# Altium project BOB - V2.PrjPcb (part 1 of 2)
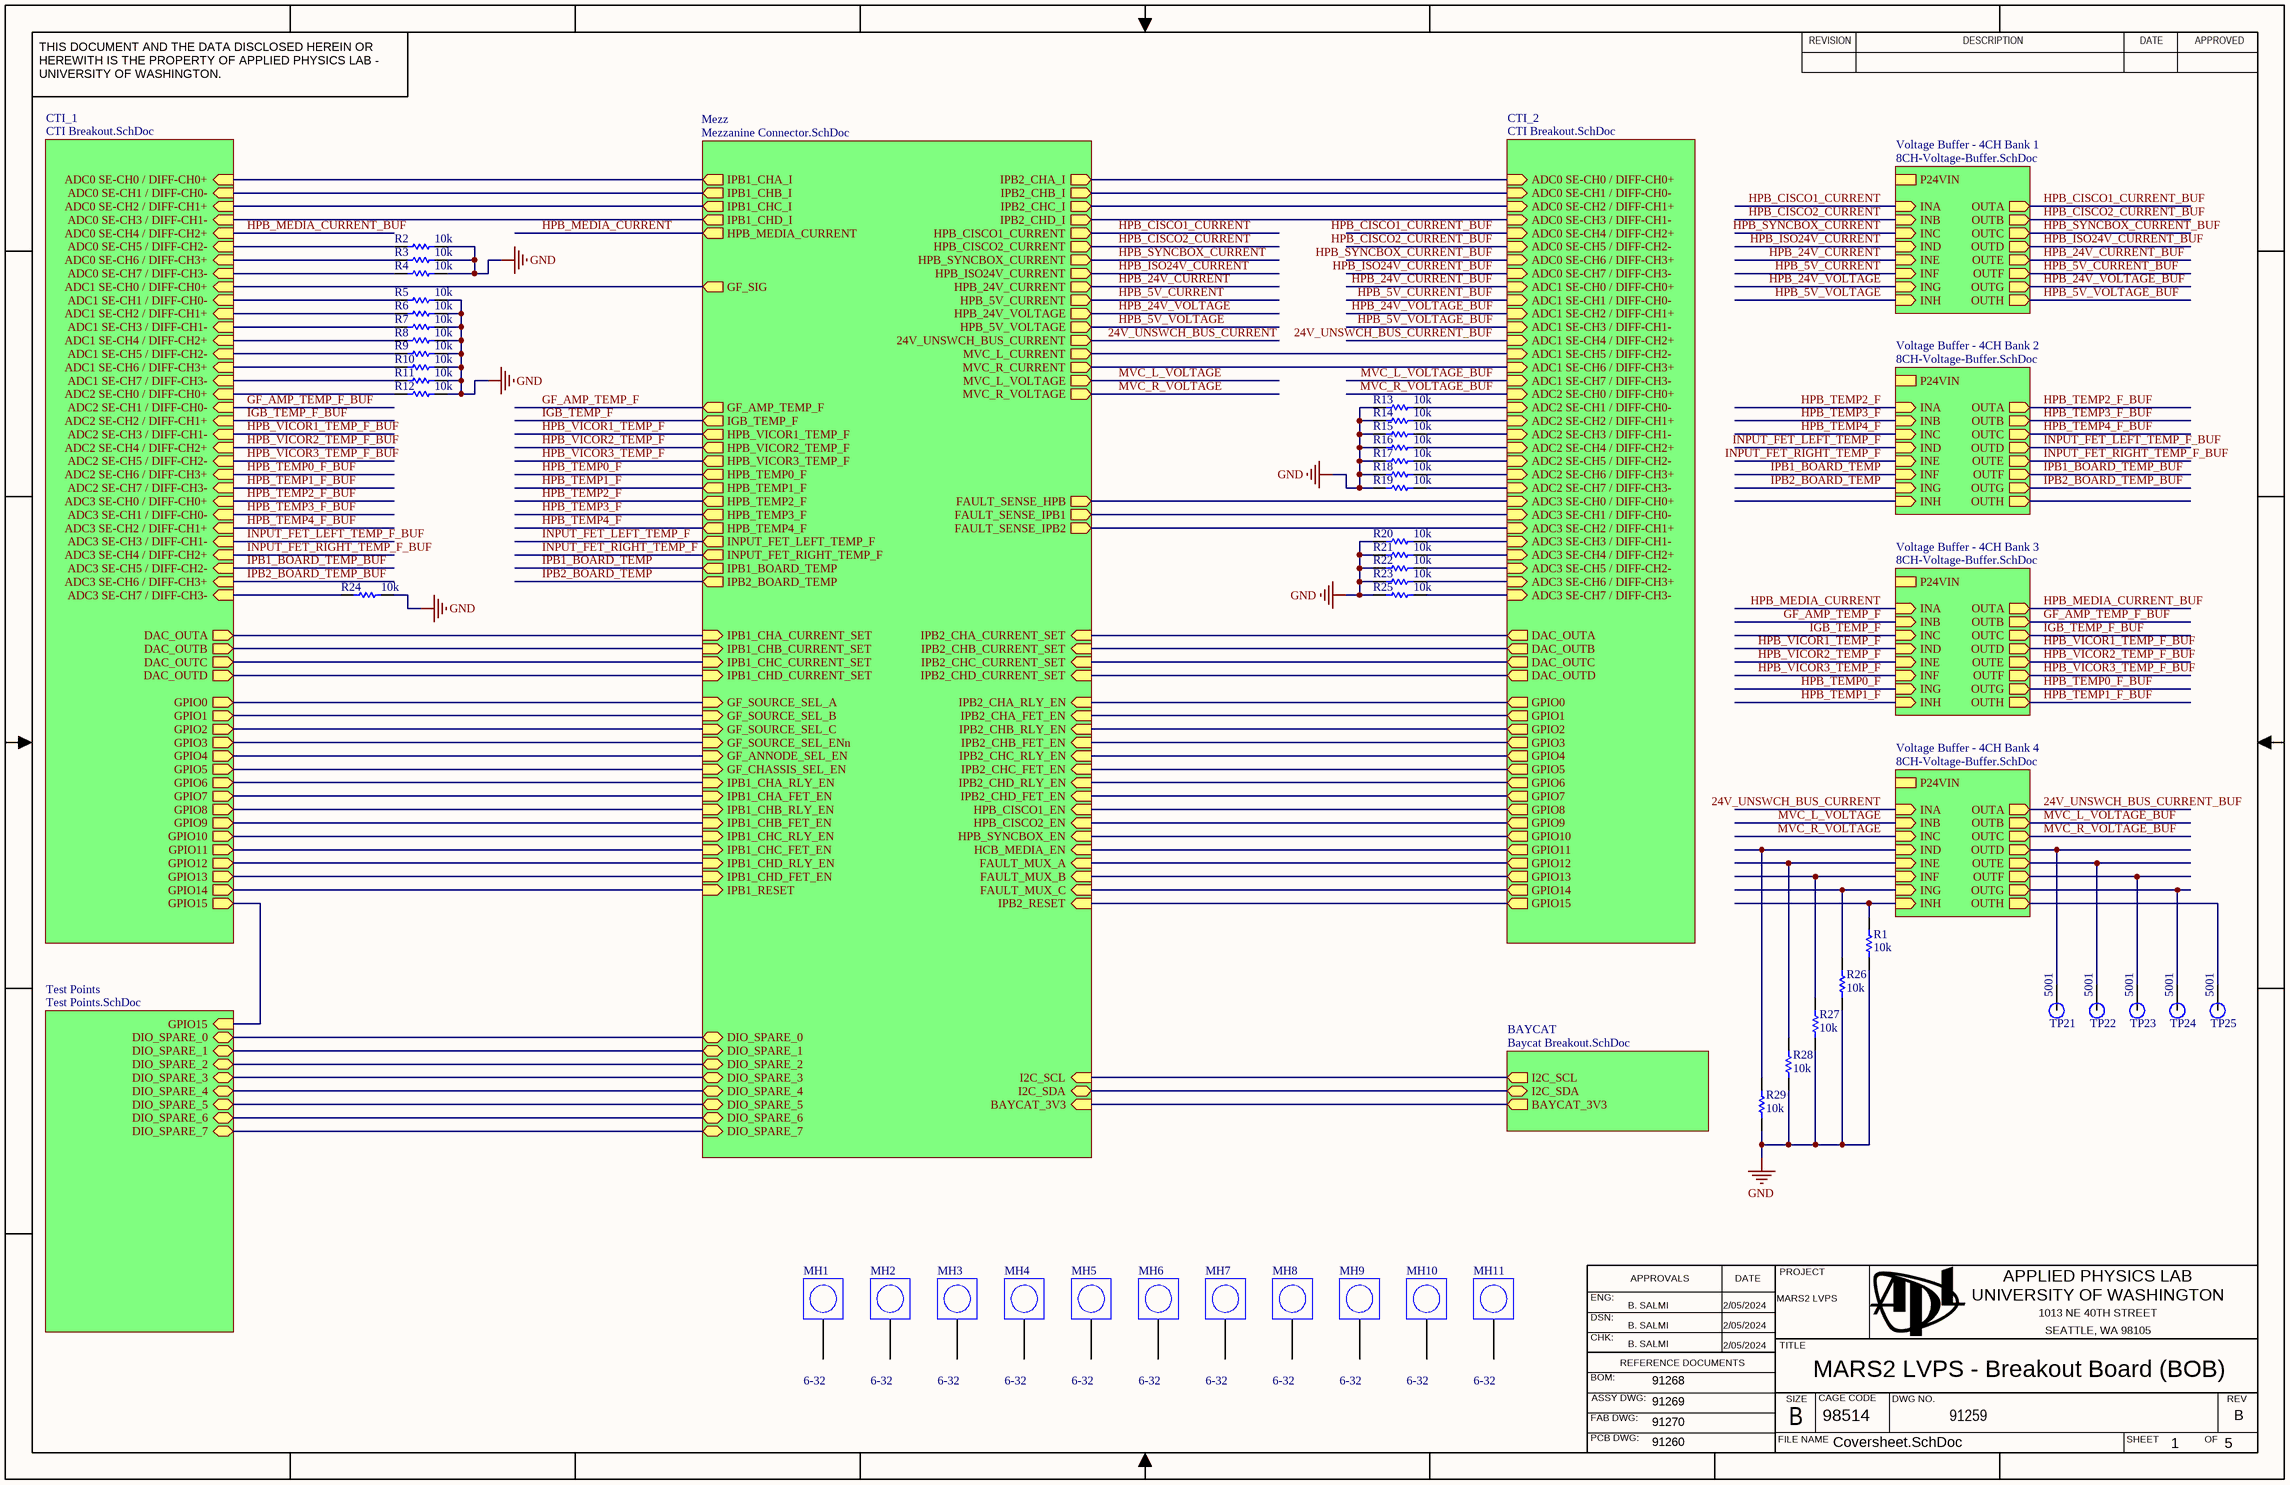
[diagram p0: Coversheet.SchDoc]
Gbl_Revision: B; Gbl_Project: MARS2 LVPS; Gbl_PCB_DWG_NO: 91260; Gbl_ENG_APP_DATE: 2/05/2024; Gbl_Engineer: B. SALMI; Gbl_DSN_APP_DATE: 2/05/2024; Gbl_DrawnBy: B. SALMI; Gbl_DOC_NO_SCH_DWG: 91259; Gbl_DOC_NO_FAB_DWG: 91270; Gbl_DOC_NO_BOM: 91268; Gbl_DOC_NO_ASSY_DWG: 91269; Gbl_CHK_APP_DATE: 2/05/2024; Gbl_CheckedBy: B. SALMI; Gbl_Cage: 98514
6 sheets, 173 parts. Net scope: hierarchical (ports join the sheet entries above them; power ports are global).
Board file: BOB.PcbDoc
Sheets:
  Coversheet.SchDoc
    Mezz = Mezzanine Connector.SchDoc
    CTI_1 = CTI Breakout.SchDoc
    CTI_2 = CTI Breakout.SchDoc
    BAYCAT = Baycat Breakout.SchDoc
    Test Points = Test Points.SchDoc
    Voltage Buffer - 4CH Bank 1 = 8CH-Voltage-Buffer.SchDoc
    Voltage Buffer - 4CH Bank 2 = 8CH-Voltage-Buffer.SchDoc
    Voltage Buffer - 4CH Bank 3 = 8CH-Voltage-Buffer.SchDoc
    Voltage Buffer - 4CH Bank 4 = 8CH-Voltage-Buffer.SchDoc

## Sheet Coversheet.SchDoc: MARS2 LVPS - Breakout Board (BOB)
size 431 x 279 mm; Organization: ORGANIZATION; Address1: APPLIED PHYSICS LAB; Address2: UNIVERSITY OF WASHINGTON; Address3: 1013 NE 40TH STREET; Address4: SEATTLE, WA 98105; DocumentNumber: 1; Revision: -; SheetNumber: 1; SheetTotal: 5; ENG_APP_DATE: --/--/--; DSN_APP_DATE: --/--/--; CHK_APP_DATE: --/--/--

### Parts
MH1  Fastener Size: 6-32  [MH-M3-Footprint-1 - Oversized MARS2]  (hidden comment: MH-MARS2-6-32)  (no BOM)
MH2  Fastener Size: 6-32  [MH-M3-Footprint-1 - Oversized MARS2]  (hidden comment: MH-MARS2-6-32)  (no BOM)
MH3  Fastener Size: 6-32  [MH-M3-Footprint-1 - Oversized MARS2]  (hidden comment: MH-MARS2-6-32)  (no BOM)
MH4  Fastener Size: 6-32  [MH-M3-Footprint-1 - Oversized MARS2]  (hidden comment: MH-MARS2-6-32)  (no BOM)
MH5  Fastener Size: 6-32  [MH-M3-Footprint-1 - Oversized MARS2]  (hidden comment: MH-MARS2-6-32)  (no BOM)
MH6  Fastener Size: 6-32  [MH-M3-Footprint-1 - Oversized MARS2]  (hidden comment: MH-MARS2-6-32)  (no BOM)
MH7  Fastener Size: 6-32  [MH-M3-Footprint-1 - Oversized MARS2]  (hidden comment: MH-MARS2-6-32)  (no BOM)
MH8  Fastener Size: 6-32  [MH-M3-Footprint-1 - Oversized MARS2]  (hidden comment: MH-MARS2-6-32)  (no BOM)
MH9  Fastener Size: 6-32  [MH-M3-Footprint-1 - Oversized MARS2]  (hidden comment: MH-MARS2-6-32)  (no BOM)
MH10  Fastener Size: 6-32  [MH-M3-Footprint-1 - Oversized MARS2]  (hidden comment: MH-MARS2-6-32)  (no BOM)
MH11  Fastener Size: 6-32  [MH-M3-Footprint-1 - Oversized MARS2]  (hidden comment: MH-MARS2-6-32)  (no BOM)
R1  value 10k  [RESC1608X55X25ML10T15]  (hidden comment: Resistor 10k +/-1% 0603 100 mW)
R2  value 10k  [RESC1608X55X25ML10T15]  (hidden comment: Resistor 10k +/-1% 0603 100 mW)
R3  value 10k  [RESC1608X55X25ML10T15]  (hidden comment: Resistor 10k +/-1% 0603 100 mW)
R4  value 10k  [RESC1608X55X25ML10T15]  (hidden comment: Resistor 10k +/-1% 0603 100 mW)
R5  value 10k  [RESC1608X55X25ML10T15]  (hidden comment: Resistor 10k +/-1% 0603 100 mW)
R6  value 10k  [RESC1608X55X25ML10T15]  (hidden comment: Resistor 10k +/-1% 0603 100 mW)
R7  value 10k  [RESC1608X55X25ML10T15]  (hidden comment: Resistor 10k +/-1% 0603 100 mW)
R8  value 10k  [RESC1608X55X25ML10T15]  (hidden comment: Resistor 10k +/-1% 0603 100 mW)
R9  value 10k  [RESC1608X55X25ML10T15]  (hidden comment: Resistor 10k +/-1% 0603 100 mW)
R10  value 10k  [RESC1608X55X25ML10T15]  (hidden comment: Resistor 10k +/-1% 0603 100 mW)
R11  value 10k  [RESC1608X55X25ML10T15]  (hidden comment: Resistor 10k +/-1% 0603 100 mW)
R12  value 10k  [RESC1608X55X25ML10T15]  (hidden comment: Resistor 10k +/-1% 0603 100 mW)
R13  value 10k  [RESC1608X55X25ML10T15]  (hidden comment: Resistor 10k +/-1% 0603 100 mW)
R14  value 10k  [RESC1608X55X25ML10T15]  (hidden comment: Resistor 10k +/-1% 0603 100 mW)
R15  value 10k  [RESC1608X55X25ML10T15]  (hidden comment: Resistor 10k +/-1% 0603 100 mW)
R16  value 10k  [RESC1608X55X25ML10T15]  (hidden comment: Resistor 10k +/-1% 0603 100 mW)
R17  value 10k  [RESC1608X55X25ML10T15]  (hidden comment: Resistor 10k +/-1% 0603 100 mW)
R18  value 10k  [RESC1608X55X25ML10T15]  (hidden comment: Resistor 10k +/-1% 0603 100 mW)
R19  value 10k  [RESC1608X55X25ML10T15]  (hidden comment: Resistor 10k +/-1% 0603 100 mW)
R20  value 10k  [RESC1608X55X25ML10T15]  (hidden comment: Resistor 10k +/-1% 0603 100 mW)
R21  value 10k  [RESC1608X55X25ML10T15]  (hidden comment: Resistor 10k +/-1% 0603 100 mW)
R22  value 10k  [RESC1608X55X25ML10T15]  (hidden comment: Resistor 10k +/-1% 0603 100 mW)
R23  value 10k  [RESC1608X55X25ML10T15]  (hidden comment: Resistor 10k +/-1% 0603 100 mW)
R24  value 10k  [RESC1608X55X25ML10T15]  (hidden comment: Resistor 10k +/-1% 0603 100 mW)
R25  value 10k  [RESC1608X55X25ML10T15]  (hidden comment: Resistor 10k +/-1% 0603 100 mW)
R26  value 10k  [RESC1608X55X25ML10T15]  (hidden comment: Resistor 10k +/-1% 0603 100 mW)
R27  value 10k  [RESC1608X55X25ML10T15]  (hidden comment: Resistor 10k +/-1% 0603 100 mW)
R28  value 10k  [RESC1608X55X25ML10T15]  (hidden comment: Resistor 10k +/-1% 0603 100 mW)
R29  value 10k  [RESC1608X55X25ML10T15]  (hidden comment: Resistor 10k +/-1% 0603 100 mW)
TP21  5001  [FP-5001-MFG]
TP22  5001  [FP-5001-MFG]
TP23  5001  [FP-5001-MFG]
TP24  5001  [FP-5001-MFG]
TP25  5001  [FP-5001-MFG]

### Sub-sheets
BAYCAT = Baycat Breakout.SchDoc: I2C_SDA (bidir), I2C_SCL (out), BAYCAT_3V3 (out)
CTI_1 = CTI Breakout.SchDoc: ADC0 SE-CH0 / DIFF-CH0+ (in), ADC0 SE-CH2 / DIFF-CH1+ (in), ADC0 SE-CH4 / DIFF-CH2+ (in), ADC0 SE-CH6 / DIFF-CH3+ (in), ADC1 SE-CH0 / DIFF-CH0+ (in), ADC1 SE-CH2 / DIFF-CH1+ (in), ADC1 SE-CH4 / DIFF-CH2+ (in), ADC1 SE-CH6 / DIFF-CH3+ (in), ADC2 SE-CH0 / DIFF-CH0+ (in), ADC2 SE-CH2 / DIFF-CH1+ (in), ADC2 SE-CH4 / DIFF-CH2+ (in), ADC2 SE-CH6 / DIFF-CH3+ (in), ADC3 SE-CH0 / DIFF-CH0+ (in), ADC3 SE-CH2 / DIFF-CH1+ (in), ADC3 SE-CH4 / DIFF-CH2+ (in), ADC3 SE-CH6 / DIFF-CH3+ (in), ADC0 SE-CH1 / DIFF-CH0- (in), ADC0 SE-CH3 / DIFF-CH1- (in), ADC0 SE-CH5 / DIFF-CH2- (in), ADC0 SE-CH7 / DIFF-CH3- (in), ADC1 SE-CH1 / DIFF-CH0- (in), ADC1 SE-CH3 / DIFF-CH1- (in), ADC1 SE-CH5 / DIFF-CH2- (in), ADC1 SE-CH7 / DIFF-CH3- (in), ADC2 SE-CH1 / DIFF-CH0- (in), ADC2 SE-CH3 / DIFF-CH1- (in), ADC2 SE-CH5 / DIFF-CH2- (in), ADC2 SE-CH7 / DIFF-CH3- (in), ADC3 SE-CH1 / DIFF-CH0- (in), ADC3 SE-CH3 / DIFF-CH1- (in), ADC3 SE-CH5 / DIFF-CH2- (in), ADC3 SE-CH7 / DIFF-CH3- (in), DAC_OUTA (out), DAC_OUTB (out), DAC_OUTC (out), DAC_OUTD (out), GPIO0 (out), GPIO2 (out), GPIO4 (out), GPIO6 (out), GPIO8 (out), GPIO10 (out), GPIO12 (out), GPIO14 (out), GPIO1 (out), GPIO3 (out), GPIO5 (out), GPIO7 (out), GPIO9 (out), GPIO11 (out), GPIO13 (out), GPIO15 (out)
CTI_2 = CTI Breakout.SchDoc: ADC0 SE-CH0 / DIFF-CH0+ (in), ADC0 SE-CH2 / DIFF-CH1+ (in), ADC0 SE-CH4 / DIFF-CH2+ (in), ADC0 SE-CH6 / DIFF-CH3+ (in), ADC1 SE-CH0 / DIFF-CH0+ (in), ADC1 SE-CH2 / DIFF-CH1+ (in), ADC1 SE-CH4 / DIFF-CH2+ (in), ADC1 SE-CH6 / DIFF-CH3+ (in), ADC2 SE-CH0 / DIFF-CH0+ (in), ADC2 SE-CH2 / DIFF-CH1+ (in), ADC2 SE-CH4 / DIFF-CH2+ (in), ADC2 SE-CH6 / DIFF-CH3+ (in), ADC3 SE-CH0 / DIFF-CH0+ (in), ADC3 SE-CH2 / DIFF-CH1+ (in), ADC3 SE-CH4 / DIFF-CH2+ (in), ADC3 SE-CH6 / DIFF-CH3+ (in), ADC0 SE-CH1 / DIFF-CH0- (in), ADC0 SE-CH3 / DIFF-CH1- (in), ADC0 SE-CH5 / DIFF-CH2- (in), ADC0 SE-CH7 / DIFF-CH3- (in), ADC1 SE-CH1 / DIFF-CH0- (in), ADC1 SE-CH3 / DIFF-CH1- (in), ADC1 SE-CH5 / DIFF-CH2- (in), ADC1 SE-CH7 / DIFF-CH3- (in), ADC2 SE-CH1 / DIFF-CH0- (in), ADC2 SE-CH3 / DIFF-CH1- (in), ADC2 SE-CH5 / DIFF-CH2- (in), ADC2 SE-CH7 / DIFF-CH3- (in), ADC3 SE-CH1 / DIFF-CH0- (in), ADC3 SE-CH3 / DIFF-CH1- (in), ADC3 SE-CH5 / DIFF-CH2- (in), ADC3 SE-CH7 / DIFF-CH3- (in), DAC_OUTA (out), DAC_OUTB (out), DAC_OUTC (out), DAC_OUTD (out), GPIO0 (out), GPIO2 (out), GPIO4 (out), GPIO6 (out), GPIO8 (out), GPIO10 (out), GPIO12 (out), GPIO14 (out), GPIO1 (out), GPIO3 (out), GPIO5 (out), GPIO7 (out), GPIO9 (out), GPIO11 (out), GPIO13 (out), GPIO15 (out)
Mezz = Mezzanine Connector.SchDoc: FAULT_SENSE_HPB (out), HPB_CISCO1_CURRENT (out), HPB_CISCO2_CURRENT (out), HPB_SYNCBOX_CURRENT (out), HPB_ISO24V_CURRENT (out), 24V_UNSWCH_BUS_CURRENT (out), HPB_24V_VOLTAGE (out), HPB_24V_CURRENT (out), HPB_5V_VOLTAGE (out), HPB_5V_CURRENT (out), FAULT_MUX_A (in), FAULT_MUX_C (in), FAULT_MUX_B (in), HPB_VICOR1_TEMP_F (out), HPB_VICOR2_TEMP_F (out), HPB_VICOR3_TEMP_F (out), HPB_TEMP0_F (out), HPB_TEMP1_F (out), HPB_TEMP2_F (out), HPB_TEMP3_F (out), HPB_TEMP4_F (out), HPB_CISCO1_EN (in), HPB_CISCO2_EN (in), HPB_SYNCBOX_EN (in), I2C_SDA (bidir), I2C_SCL (in), HCB_MEDIA_EN (in), DIO_SPARE_0 (bidir), DIO_SPARE_1 (bidir), DIO_SPARE_2 (bidir), DIO_SPARE_3 (bidir), DIO_SPARE_4 (bidir), DIO_SPARE_5 (bidir), DIO_SPARE_6 (bidir), DIO_SPARE_7 (bidir), IPB1_BOARD_TEMP (out), IPB2_BOARD_TEMP (out), BAYCAT_3V3 (in), IPB1_CHA_CURRENT_SET (in), IPB2_CHA_CURRENT_SET (in), IPB1_CHB_CURRENT_SET (in), IPB2_CHB_CURRENT_SET (in), IPB1_CHC_CURRENT_SET (in), IPB2_CHC_CURRENT_SET (in), IPB1_CHD_CURRENT_SET (in), IPB2_CHD_CURRENT_SET (in), IPB1_CHA_RLY_EN (in), IPB2_CHA_RLY_EN (in), IPB1_CHA_FET_EN (in), IPB2_CHA_FET_EN (in), IPB1_CHB_RLY_EN (in), IPB2_CHB_RLY_EN (in), IPB1_CHB_FET_EN (in), IPB2_CHB_FET_EN (in), IPB1_CHC_RLY_EN (in), IPB2_CHC_RLY_EN (in), IPB1_CHC_FET_EN (in), IPB2_CHC_FET_EN (in), IPB1_CHD_RLY_EN (in), IPB2_CHD_RLY_EN (in), IPB1_CHD_FET_EN (in), IPB2_CHD_FET_EN (in), IPB1_RESET (in), IPB2_RESET (in), MVC_R_CURRENT (out), MVC_L_CURRENT (out), MVC_R_VOLTAGE (out), MVC_L_VOLTAGE (out), GF_SOURCE_SEL_A (in), GF_SOURCE_SEL_B (in), GF_SOURCE_SEL_C (in), GF_SOURCE_SEL_ENn (in), GF_ANNODE_SEL_EN (in), GF_CHASSIS_SEL_EN (in), IPB1_CHA_I (out), IPB2_CHA_I (out), IPB1_CHB_I (out), IPB2_CHB_I (out), IPB1_CHC_I (out), IPB2_CHC_I (out), IPB1_CHD_I (out), IPB2_CHD_I (out), GF_SIG (out), FAULT_SENSE_IPB1 (out), IGB_TEMP_F (out), GF_AMP_TEMP_F (out), INPUT_FET_RIGHT_TEMP_F (out), INPUT_FET_LEFT_TEMP_F (out), FAULT_SENSE_IPB2 (out), HPB_MEDIA_CURRENT (out)
Test Points = Test Points.SchDoc: DIO_SPARE_0 (bidir), DIO_SPARE_1 (bidir), DIO_SPARE_2 (bidir), DIO_SPARE_3 (bidir), DIO_SPARE_4 (bidir), DIO_SPARE_5 (bidir), DIO_SPARE_6 (bidir), DIO_SPARE_7 (bidir), GPIO15 (in)
Voltage Buffer - 4CH Bank 1 = 8CH-Voltage-Buffer.SchDoc: P24VIN, INA (in), INB (in), INC (in), IND (in), INE (in), INF (in), ING (in), INH (in), OUTA (out), OUTB (out), OUTC (out), OUTD (out), OUTE (out), OUTF (out), OUTG (out), OUTH (out)
Voltage Buffer - 4CH Bank 2 = 8CH-Voltage-Buffer.SchDoc: P24VIN, INA (in), INB (in), INC (in), IND (in), INE (in), INF (in), ING (in), INH (in), OUTA (out), OUTB (out), OUTC (out), OUTD (out), OUTE (out), OUTF (out), OUTG (out), OUTH (out)
Voltage Buffer - 4CH Bank 3 = 8CH-Voltage-Buffer.SchDoc: P24VIN, INA (in), INB (in), INC (in), IND (in), INE (in), INF (in), ING (in), INH (in), OUTA (out), OUTB (out), OUTC (out), OUTD (out), OUTE (out), OUTF (out), OUTG (out), OUTH (out)
Voltage Buffer - 4CH Bank 4 = 8CH-Voltage-Buffer.SchDoc: P24VIN, INA (in), INB (in), INC (in), IND (in), INE (in), INF (in), ING (in), INH (in), OUTA (out), OUTB (out), OUTC (out), OUTD (out), OUTE (out), OUTF (out), OUTG (out), OUTH (out)

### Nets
GND: R1.1 R2.2 R3.2 R4.2 R5.2 R6.2 R7.2 R8.2 R9.2 R10.2 R11.2 R12.2 R13.1 R14.1 R15.1 R16.1 R17.1 R18.1 R19.1 R20.1 R21.1 R22.1 R23.1 R24.2 R25.1 R26.1 R27.1 R28.1 R29.1
24V_UNSWCH_BUS_CURRENT: sheet Mezz/24V_UNSWCH_BUS_CURRENT, sheet Voltage Buffer - 4CH Bank 4/INA
24V_UNSWCH_BUS_CURRENT_BUF: sheet CTI_2/ADC1 SE-CH4 / DIFF-CH2+, sheet Voltage Buffer - 4CH Bank 4/OUTA
BAYCAT_3V3: sheet Mezz/BAYCAT_3V3, sheet BAYCAT/BAYCAT_3V3
DIO_SPARE_0: sheet Mezz/DIO_SPARE_0, sheet Test Points/DIO_SPARE_0
DIO_SPARE_1: sheet Mezz/DIO_SPARE_1, sheet Test Points/DIO_SPARE_1
DIO_SPARE_2: sheet Mezz/DIO_SPARE_2, sheet Test Points/DIO_SPARE_2
DIO_SPARE_3: sheet Mezz/DIO_SPARE_3, sheet Test Points/DIO_SPARE_3
DIO_SPARE_4: sheet Mezz/DIO_SPARE_4, sheet Test Points/DIO_SPARE_4
DIO_SPARE_5: sheet Mezz/DIO_SPARE_5, sheet Test Points/DIO_SPARE_5
DIO_SPARE_6: sheet Mezz/DIO_SPARE_6, sheet Test Points/DIO_SPARE_6
DIO_SPARE_7: sheet Mezz/DIO_SPARE_7, sheet Test Points/DIO_SPARE_7
FAULT_MUX_A: sheet Mezz/FAULT_MUX_A, sheet CTI_2/GPIO12
FAULT_MUX_B: sheet Mezz/FAULT_MUX_B, sheet CTI_2/GPIO13
FAULT_MUX_C: sheet Mezz/FAULT_MUX_C, sheet CTI_2/GPIO14
FAULT_SENSE_HPB: sheet Mezz/FAULT_SENSE_HPB, sheet CTI_2/ADC3 SE-CH0 / DIFF-CH0+
FAULT_SENSE_IPB1: sheet Mezz/FAULT_SENSE_IPB1, sheet CTI_2/ADC3 SE-CH1 / DIFF-CH0-
FAULT_SENSE_IPB2: sheet Mezz/FAULT_SENSE_IPB2, sheet CTI_2/ADC3 SE-CH2 / DIFF-CH1+
GF_AMP_TEMP_F: sheet Mezz/GF_AMP_TEMP_F, sheet Voltage Buffer - 4CH Bank 3/INB
GF_AMP_TEMP_F_BUF: sheet CTI_1/ADC2 SE-CH1 / DIFF-CH0-, sheet Voltage Buffer - 4CH Bank 3/OUTB
GF_ANNODE_SEL_EN: sheet Mezz/GF_ANNODE_SEL_EN, sheet CTI_1/GPIO4
GF_CHASSIS_SEL_EN: sheet Mezz/GF_CHASSIS_SEL_EN, sheet CTI_1/GPIO5
GF_SIG: sheet Mezz/GF_SIG, sheet CTI_1/ADC1 SE-CH0 / DIFF-CH0+
GF_SOURCE_SEL_A: sheet Mezz/GF_SOURCE_SEL_A, sheet CTI_1/GPIO0
GF_SOURCE_SEL_B: sheet Mezz/GF_SOURCE_SEL_B, sheet CTI_1/GPIO1
GF_SOURCE_SEL_C: sheet Mezz/GF_SOURCE_SEL_C, sheet CTI_1/GPIO2
GF_SOURCE_SEL_ENn: sheet Mezz/GF_SOURCE_SEL_ENn, sheet CTI_1/GPIO3
HCB_MEDIA_EN: sheet Mezz/HCB_MEDIA_EN, sheet CTI_2/GPIO11
HPB_5V_CURRENT: sheet Mezz/HPB_5V_CURRENT, sheet Voltage Buffer - 4CH Bank 1/INF
HPB_5V_CURRENT_BUF: sheet CTI_2/ADC1 SE-CH1 / DIFF-CH0-, sheet Voltage Buffer - 4CH Bank 1/OUTF
HPB_5V_VOLTAGE: sheet Mezz/HPB_5V_VOLTAGE, sheet Voltage Buffer - 4CH Bank 1/INH
HPB_5V_VOLTAGE_BUF: sheet CTI_2/ADC1 SE-CH3 / DIFF-CH1-, sheet Voltage Buffer - 4CH Bank 1/OUTH
HPB_24V_CURRENT: sheet Mezz/HPB_24V_CURRENT, sheet Voltage Buffer - 4CH Bank 1/INE
HPB_24V_CURRENT_BUF: sheet CTI_2/ADC1 SE-CH0 / DIFF-CH0+, sheet Voltage Buffer - 4CH Bank 1/OUTE
HPB_24V_VOLTAGE: sheet Mezz/HPB_24V_VOLTAGE, sheet Voltage Buffer - 4CH Bank 1/ING
HPB_24V_VOLTAGE_BUF: sheet CTI_2/ADC1 SE-CH2 / DIFF-CH1+, sheet Voltage Buffer - 4CH Bank 1/OUTG
HPB_CISCO1_CURRENT: sheet Mezz/HPB_CISCO1_CURRENT, sheet Voltage Buffer - 4CH Bank 1/INA
HPB_CISCO1_CURRENT_BUF: sheet CTI_2/ADC0 SE-CH4 / DIFF-CH2+, sheet Voltage Buffer - 4CH Bank 1/OUTA
HPB_CISCO1_EN: sheet Mezz/HPB_CISCO1_EN, sheet CTI_2/GPIO8
HPB_CISCO2_CURRENT: sheet Mezz/HPB_CISCO2_CURRENT, sheet Voltage Buffer - 4CH Bank 1/INB
HPB_CISCO2_CURRENT_BUF: sheet CTI_2/ADC0 SE-CH5 / DIFF-CH2-, sheet Voltage Buffer - 4CH Bank 1/OUTB
HPB_CISCO2_EN: sheet Mezz/HPB_CISCO2_EN, sheet CTI_2/GPIO9
HPB_ISO24V_CURRENT: sheet Mezz/HPB_ISO24V_CURRENT, sheet Voltage Buffer - 4CH Bank 1/IND
HPB_ISO24V_CURRENT_BUF: sheet CTI_2/ADC0 SE-CH7 / DIFF-CH3-, sheet Voltage Buffer - 4CH Bank 1/OUTD
HPB_MEDIA_CURRENT: sheet Mezz/HPB_MEDIA_CURRENT, sheet Voltage Buffer - 4CH Bank 3/INA
HPB_MEDIA_CURRENT_BUF: sheet CTI_1/ADC0 SE-CH4 / DIFF-CH2+, sheet Voltage Buffer - 4CH Bank 3/OUTA
HPB_SYNCBOX_CURRENT: sheet Mezz/HPB_SYNCBOX_CURRENT, sheet Voltage Buffer - 4CH Bank 1/INC
HPB_SYNCBOX_CURRENT_BUF: sheet CTI_2/ADC0 SE-CH6 / DIFF-CH3+, sheet Voltage Buffer - 4CH Bank 1/OUTC
HPB_SYNCBOX_EN: sheet Mezz/HPB_SYNCBOX_EN, sheet CTI_2/GPIO10
HPB_TEMP0_F: sheet Mezz/HPB_TEMP0_F, sheet Voltage Buffer - 4CH Bank 3/ING  [project net HPB_TEMP0]
HPB_TEMP0_F_BUF: sheet CTI_1/ADC2 SE-CH6 / DIFF-CH3+, sheet Voltage Buffer - 4CH Bank 3/OUTG
HPB_TEMP1_F: sheet Mezz/HPB_TEMP1_F, sheet Voltage Buffer - 4CH Bank 3/INH  [project net HPB_TEMP1]
HPB_TEMP1_F_BUF: sheet CTI_1/ADC2 SE-CH7 / DIFF-CH3-, sheet Voltage Buffer - 4CH Bank 3/OUTH
HPB_TEMP2_F: sheet Mezz/HPB_TEMP2_F, sheet Voltage Buffer - 4CH Bank 2/INA  [project net HPB_TEMP2]
HPB_TEMP2_F_BUF: sheet CTI_1/ADC3 SE-CH0 / DIFF-CH0+, sheet Voltage Buffer - 4CH Bank 2/OUTA
HPB_TEMP3_F: sheet Mezz/HPB_TEMP3_F, sheet Voltage Buffer - 4CH Bank 2/INB  [project net HPB_TEMP3]
HPB_TEMP3_F_BUF: sheet CTI_1/ADC3 SE-CH1 / DIFF-CH0-, sheet Voltage Buffer - 4CH Bank 2/OUTB
HPB_TEMP4_F: sheet Mezz/HPB_TEMP4_F, sheet Voltage Buffer - 4CH Bank 2/INC  [project net HPB_TEMP4]
HPB_TEMP4_F_BUF: sheet CTI_1/ADC3 SE-CH2 / DIFF-CH1+, sheet Voltage Buffer - 4CH Bank 2/OUTC
HPB_VICOR1_TEMP_F: sheet Mezz/HPB_VICOR1_TEMP_F, sheet Voltage Buffer - 4CH Bank 3/IND  [project net HPB_VICOR1_TEMP]
HPB_VICOR1_TEMP_F_BUF: sheet CTI_1/ADC2 SE-CH3 / DIFF-CH1-, sheet Voltage Buffer - 4CH Bank 3/OUTD
HPB_VICOR2_TEMP_F: sheet Mezz/HPB_VICOR2_TEMP_F, sheet Voltage Buffer - 4CH Bank 3/INE  [project net HPB_VICOR2_TEMP]
HPB_VICOR2_TEMP_F_BUF: sheet CTI_1/ADC2 SE-CH4 / DIFF-CH2+, sheet Voltage Buffer - 4CH Bank 3/OUTE
HPB_VICOR3_TEMP_F: sheet Mezz/HPB_VICOR3_TEMP_F, sheet Voltage Buffer - 4CH Bank 3/INF  [project net HPB_VICOR3_TEMP]
HPB_VICOR3_TEMP_F_BUF: sheet CTI_1/ADC2 SE-CH5 / DIFF-CH2-, sheet Voltage Buffer - 4CH Bank 3/OUTF
I2C_SCL: sheet Mezz/I2C_SCL, sheet BAYCAT/I2C_SCL
I2C_SDA: sheet Mezz/I2C_SDA, sheet BAYCAT/I2C_SDA
IGB_TEMP_F: sheet Mezz/IGB_TEMP_F, sheet Voltage Buffer - 4CH Bank 3/INC
IGB_TEMP_F_BUF: sheet CTI_1/ADC2 SE-CH2 / DIFF-CH1+, sheet Voltage Buffer - 4CH Bank 3/OUTC
INPUT_FET_LEFT_TEMP_F: sheet Mezz/INPUT_FET_LEFT_TEMP_F, sheet Voltage Buffer - 4CH Bank 2/IND
INPUT_FET_LEFT_TEMP_F_BUF: sheet CTI_1/ADC3 SE-CH3 / DIFF-CH1-, sheet Voltage Buffer - 4CH Bank 2/OUTD
INPUT_FET_RIGHT_TEMP_F: sheet Mezz/INPUT_FET_RIGHT_TEMP_F, sheet Voltage Buffer - 4CH Bank 2/INE
INPUT_FET_RIGHT_TEMP_F_BUF: sheet CTI_1/ADC3 SE-CH4 / DIFF-CH2+, sheet Voltage Buffer - 4CH Bank 2/OUTE
IPB1_BOARD_TEMP: sheet Mezz/IPB1_BOARD_TEMP, sheet Voltage Buffer - 4CH Bank 2/INF
IPB1_BOARD_TEMP_BUF: sheet CTI_1/ADC3 SE-CH5 / DIFF-CH2-, sheet Voltage Buffer - 4CH Bank 2/OUTF
IPB1_CHA_CURRENT_SET: sheet Mezz/IPB1_CHA_CURRENT_SET, sheet CTI_1/DAC_OUTA
IPB1_CHA_FET_EN: sheet Mezz/IPB1_CHA_FET_EN, sheet CTI_1/GPIO7
IPB1_CHA_I: sheet Mezz/IPB1_CHA_I, sheet CTI_1/ADC0 SE-CH0 / DIFF-CH0+
IPB1_CHA_RLY_EN: sheet Mezz/IPB1_CHA_RLY_EN, sheet CTI_1/GPIO6
IPB1_CHB_CURRENT_SET: sheet Mezz/IPB1_CHB_CURRENT_SET, sheet CTI_1/DAC_OUTB
IPB1_CHB_FET_EN: sheet Mezz/IPB1_CHB_FET_EN, sheet CTI_1/GPIO9
IPB1_CHB_I: sheet Mezz/IPB1_CHB_I, sheet CTI_1/ADC0 SE-CH1 / DIFF-CH0-
IPB1_CHB_RLY_EN: sheet Mezz/IPB1_CHB_RLY_EN, sheet CTI_1/GPIO8
IPB1_CHC_CURRENT_SET: sheet Mezz/IPB1_CHC_CURRENT_SET, sheet CTI_1/DAC_OUTC
IPB1_CHC_FET_EN: sheet Mezz/IPB1_CHC_FET_EN, sheet CTI_1/GPIO11
IPB1_CHC_I: sheet Mezz/IPB1_CHC_I, sheet CTI_1/ADC0 SE-CH2 / DIFF-CH1+
IPB1_CHC_RLY_EN: sheet Mezz/IPB1_CHC_RLY_EN, sheet CTI_1/GPIO10
IPB1_CHD_CURRENT_SET: sheet Mezz/IPB1_CHD_CURRENT_SET, sheet CTI_1/DAC_OUTD
IPB1_CHD_FET_EN: sheet Mezz/IPB1_CHD_FET_EN, sheet CTI_1/GPIO13
IPB1_CHD_I: sheet Mezz/IPB1_CHD_I, sheet CTI_1/ADC0 SE-CH3 / DIFF-CH1-
IPB1_CHD_RLY_EN: sheet Mezz/IPB1_CHD_RLY_EN, sheet CTI_1/GPIO12
IPB1_RESET: sheet Mezz/IPB1_RESET, sheet CTI_1/GPIO14
IPB2_BOARD_TEMP: sheet Mezz/IPB2_BOARD_TEMP, sheet Voltage Buffer - 4CH Bank 2/ING
IPB2_BOARD_TEMP_BUF: sheet CTI_1/ADC3 SE-CH6 / DIFF-CH3+, sheet Voltage Buffer - 4CH Bank 2/OUTG
IPB2_CHA_CURRENT_SET: sheet Mezz/IPB2_CHA_CURRENT_SET, sheet CTI_2/DAC_OUTA
IPB2_CHA_FET_EN: sheet Mezz/IPB2_CHA_FET_EN, sheet CTI_2/GPIO1
IPB2_CHA_I: sheet Mezz/IPB2_CHA_I, sheet CTI_2/ADC0 SE-CH0 / DIFF-CH0+
IPB2_CHA_RLY_EN: sheet Mezz/IPB2_CHA_RLY_EN, sheet CTI_2/GPIO0
IPB2_CHB_CURRENT_SET: sheet Mezz/IPB2_CHB_CURRENT_SET, sheet CTI_2/DAC_OUTB
IPB2_CHB_FET_EN: sheet Mezz/IPB2_CHB_FET_EN, sheet CTI_2/GPIO3
IPB2_CHB_I: sheet Mezz/IPB2_CHB_I, sheet CTI_2/ADC0 SE-CH1 / DIFF-CH0-
IPB2_CHB_RLY_EN: sheet Mezz/IPB2_CHB_RLY_EN, sheet CTI_2/GPIO2
IPB2_CHC_CURRENT_SET: sheet Mezz/IPB2_CHC_CURRENT_SET, sheet CTI_2/DAC_OUTC
IPB2_CHC_FET_EN: sheet Mezz/IPB2_CHC_FET_EN, sheet CTI_2/GPIO5
IPB2_CHC_I: sheet Mezz/IPB2_CHC_I, sheet CTI_2/ADC0 SE-CH2 / DIFF-CH1+
IPB2_CHC_RLY_EN: sheet Mezz/IPB2_CHC_RLY_EN, sheet CTI_2/GPIO4
IPB2_CHD_CURRENT_SET: sheet Mezz/IPB2_CHD_CURRENT_SET, sheet CTI_2/DAC_OUTD
IPB2_CHD_FET_EN: sheet Mezz/IPB2_CHD_FET_EN, sheet CTI_2/GPIO7
IPB2_CHD_I: sheet Mezz/IPB2_CHD_I, sheet CTI_2/ADC0 SE-CH3 / DIFF-CH1-
IPB2_CHD_RLY_EN: sheet Mezz/IPB2_CHD_RLY_EN, sheet CTI_2/GPIO6
IPB2_RESET: sheet Mezz/IPB2_RESET, sheet CTI_2/GPIO15
MVC_L_CURRENT: sheet Mezz/MVC_L_CURRENT, sheet CTI_2/ADC1 SE-CH5 / DIFF-CH2-
MVC_L_VOLTAGE: sheet Mezz/MVC_L_VOLTAGE, sheet Voltage Buffer - 4CH Bank 4/INB
MVC_L_VOLTAGE_BUF: sheet CTI_2/ADC1 SE-CH7 / DIFF-CH3-, sheet Voltage Buffer - 4CH Bank 4/OUTB
MVC_R_CURRENT: sheet Mezz/MVC_R_CURRENT, sheet CTI_2/ADC1 SE-CH6 / DIFF-CH3+
MVC_R_VOLTAGE: sheet Mezz/MVC_R_VOLTAGE, sheet Voltage Buffer - 4CH Bank 4/INC
MVC_R_VOLTAGE_BUF: sheet CTI_2/ADC2 SE-CH0 / DIFF-CH0+, sheet Voltage Buffer - 4CH Bank 4/OUTC
NetJ19_1: sheet CTI_1/GPIO15, sheet Test Points/GPIO15
NetP1A_6: R2.1 ; sheet CTI_1/ADC0 SE-CH5 / DIFF-CH2-
NetP1A_7: R3.1 ; sheet CTI_1/ADC0 SE-CH6 / DIFF-CH3+
NetP1A_8: R4.1 ; sheet CTI_1/ADC0 SE-CH7 / DIFF-CH3-
NetP1A_12: R5.1 ; sheet CTI_1/ADC1 SE-CH1 / DIFF-CH0-
NetP1A_13: R6.1 ; sheet CTI_1/ADC1 SE-CH2 / DIFF-CH1+
NetP1A_14: R7.1 ; sheet CTI_1/ADC1 SE-CH3 / DIFF-CH1-
NetP1A_15: R8.1 ; sheet CTI_1/ADC1 SE-CH4 / DIFF-CH2+
NetP1A_16: R9.1 ; sheet CTI_1/ADC1 SE-CH5 / DIFF-CH2-
NetP1A_17: R10.1 ; sheet CTI_1/ADC1 SE-CH6 / DIFF-CH3+
NetP1A_18: R11.1 ; sheet CTI_1/ADC1 SE-CH7 / DIFF-CH3-
NetP1A_21: R12.1 ; sheet CTI_1/ADC2 SE-CH0 / DIFF-CH0+
NetP1A_38: R24.1 ; sheet CTI_1/ADC3 SE-CH7 / DIFF-CH3-
NetP1B_22: R13.2 ; sheet CTI_2/ADC2 SE-CH1 / DIFF-CH0-
NetP1B_23: R14.2 ; sheet CTI_2/ADC2 SE-CH2 / DIFF-CH1+
NetP1B_24: R15.2 ; sheet CTI_2/ADC2 SE-CH3 / DIFF-CH1-
NetP1B_25: R16.2 ; sheet CTI_2/ADC2 SE-CH4 / DIFF-CH2+
NetP1B_26: R17.2 ; sheet CTI_2/ADC2 SE-CH5 / DIFF-CH2-
NetP1B_27: R18.2 ; sheet CTI_2/ADC2 SE-CH6 / DIFF-CH3+
NetP1B_28: R19.2 ; sheet CTI_2/ADC2 SE-CH7 / DIFF-CH3-
NetP1B_34: R20.2 ; sheet CTI_2/ADC3 SE-CH3 / DIFF-CH1-
NetP1B_35: R21.2 ; sheet CTI_2/ADC3 SE-CH4 / DIFF-CH2+
NetP1B_36: R22.2 ; sheet CTI_2/ADC3 SE-CH5 / DIFF-CH2-
NetP1B_37: R23.2 ; sheet CTI_2/ADC3 SE-CH6 / DIFF-CH3+
NetP1B_38: R25.2 ; sheet CTI_2/ADC3 SE-CH7 / DIFF-CH3-
NetR1_2: R1.2 ; sheet Voltage Buffer - 4CH Bank 4/INH
NetR26_2: R26.2 ; sheet Voltage Buffer - 4CH Bank 4/ING
NetR27_2: R27.2 ; sheet Voltage Buffer - 4CH Bank 4/INF
NetR28_2: R28.2 ; sheet Voltage Buffer - 4CH Bank 4/INE
NetR29_2: R29.2 ; sheet Voltage Buffer - 4CH Bank 4/IND
NetTP3D_1: TP22.1 ; sheet Voltage Buffer - 4CH Bank 4/OUTE
NetTP7D_1: TP23.1 ; sheet Voltage Buffer - 4CH Bank 4/OUTF
NetTP11D_1: TP24.1 ; sheet Voltage Buffer - 4CH Bank 4/OUTG
NetTP15D_1: TP25.1 ; sheet Voltage Buffer - 4CH Bank 4/OUTH
NetTP16D_1: TP21.1 ; sheet Voltage Buffer - 4CH Bank 4/OUTD

Not connected (* = marked no-connect by the designer): MH1 1; MH2 1; MH3 1; MH4 1; MH5 1; MH6 1; MH7 1; MH8 1; MH9 1; MH10 1; MH11 1

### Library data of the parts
MH1-MH11 = CMP-00028-00015-1: MARS2 Project 6-32 Mounting Hole Plated .; Plated: Yes
R1-R29 = CMP-009-00017-7: Chip Resistor, 10 KOhm, +/- 1%, 01 W, -55 to 155 degC, 0603 (1608 Metric); Voltage Rating: 50V; Power: 100mW
TP21-TP25 = CMP-001-0002-3: TEST POINT PC MINI .040D BLACK

## Sheet Mezzanine Connector.SchDoc: MARS2 LVPS - BOB - Mezzanine Conn
size 431 x 279 mm; Organization: ORGANIZATION; Address1: APPLIED PHYSICS LAB; Address2: UNIVERSITY OF WASHINGTON; Address3: 1013 NE 40TH STREET; Address4: SEATTLE, WA 98105; DocumentNumber: 2; Revision: -; SheetNumber: 2; SheetTotal: 5; ENG_APP_DATE: --/--/--; DSN_APP_DATE: --/--/--; CHK_APP_DATE: --/--/--
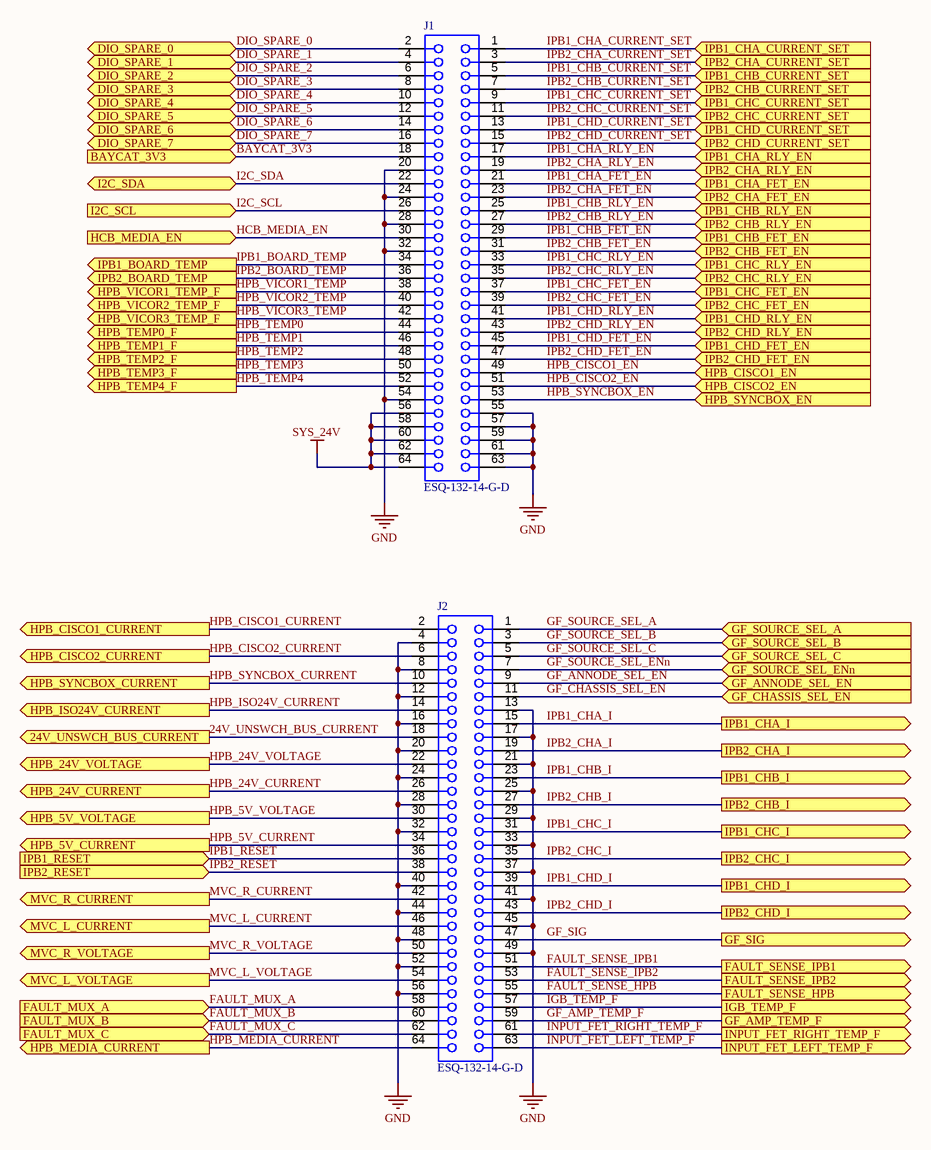
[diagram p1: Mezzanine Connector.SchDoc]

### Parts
J1  ESQ-132-14-G-D  [SMTC-ESQ-132-14-X-D]
J2  ESQ-132-14-G-D  [SMTC-ESQ-132-14-X-D]

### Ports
24V_UNSWCH_BUS_CURRENT (out), BAYCAT_3V3 (in), DIO_SPARE_0 (bidir), DIO_SPARE_1 (bidir), DIO_SPARE_2 (bidir), DIO_SPARE_3 (bidir), DIO_SPARE_4 (bidir), DIO_SPARE_5 (bidir), DIO_SPARE_6 (bidir), DIO_SPARE_7 (bidir), FAULT_MUX_A (in), FAULT_MUX_B (in), FAULT_MUX_C (in), FAULT_SENSE_HPB (out), FAULT_SENSE_IPB1 (out), FAULT_SENSE_IPB2 (out), GF_AMP_TEMP_F (out), GF_ANNODE_SEL_EN (in), GF_CHASSIS_SEL_EN (in), GF_SIG (out), GF_SOURCE_SEL_A (in), GF_SOURCE_SEL_B (in), GF_SOURCE_SEL_C (in), GF_SOURCE_SEL_ENn (in), HCB_MEDIA_EN (in), HPB_5V_CURRENT (out), HPB_5V_VOLTAGE (out), HPB_24V_CURRENT (out), HPB_24V_VOLTAGE (out), HPB_CISCO1_CURRENT (out), HPB_CISCO1_EN (in), HPB_CISCO2_CURRENT (out), HPB_CISCO2_EN (in), HPB_ISO24V_CURRENT (out), HPB_MEDIA_CURRENT (out), HPB_SYNCBOX_CURRENT (out), HPB_SYNCBOX_EN (in), HPB_TEMP0_F (out), HPB_TEMP1_F (out), HPB_TEMP2_F (out), HPB_TEMP3_F (out), HPB_TEMP4_F (out), HPB_VICOR1_TEMP_F (out), HPB_VICOR2_TEMP_F (out), HPB_VICOR3_TEMP_F (out), I2C_SCL (in), I2C_SDA (bidir), IGB_TEMP_F (out), INPUT_FET_LEFT_TEMP_F (out), INPUT_FET_RIGHT_TEMP_F (out), IPB1_BOARD_TEMP (out), IPB1_CHA_CURRENT_SET (in), IPB1_CHA_FET_EN (in), IPB1_CHA_I (out), IPB1_CHA_RLY_EN (in), IPB1_CHB_CURRENT_SET (in), IPB1_CHB_FET_EN (in), IPB1_CHB_I (out), IPB1_CHB_RLY_EN (in), IPB1_CHC_CURRENT_SET (in), IPB1_CHC_FET_EN (in), IPB1_CHC_I (out), IPB1_CHC_RLY_EN (in), IPB1_CHD_CURRENT_SET (in), IPB1_CHD_FET_EN (in), IPB1_CHD_I (out), IPB1_CHD_RLY_EN (in), IPB1_RESET (in), IPB2_BOARD_TEMP (out), IPB2_CHA_CURRENT_SET (in), IPB2_CHA_FET_EN (in), IPB2_CHA_I (out), IPB2_CHA_RLY_EN (in), IPB2_CHB_CURRENT_SET (in), IPB2_CHB_FET_EN (in), IPB2_CHB_I (out), IPB2_CHB_RLY_EN (in), IPB2_CHC_CURRENT_SET (in), IPB2_CHC_FET_EN (in), IPB2_CHC_I (out), IPB2_CHC_RLY_EN (in), IPB2_CHD_CURRENT_SET (in), IPB2_CHD_FET_EN (in), IPB2_CHD_I (out), IPB2_CHD_RLY_EN (in), IPB2_RESET (in), MVC_L_CURRENT (out), MVC_L_VOLTAGE (out), MVC_R_CURRENT (out), MVC_R_VOLTAGE (out)

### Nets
GND: J1.20 J1.24 J1.28 J1.32 J1.54 J1.55 J1.57 J1.59 J1.61 J1.63 J2.4 J2.8 J2.12 J2.13 J2.16 J2.17 J2.20 J2.21 J2.24 J2.25 J2.28 J2.29 J2.32 J2.33 J2.37 J2.40 J2.41 J2.44 J2.45 J2.48 J2.49 J2.52 J2.56
SYS_24V: J1.56 J1.58 J1.60 J1.62 J1.64
24V_UNSWCH_BUS_CURRENT: J2.18 ; port 24V_UNSWCH_BUS_CURRENT
BAYCAT_3V3: J1.18 ; port BAYCAT_3V3
DIO_SPARE_0: J1.2 ; port DIO_SPARE_0
DIO_SPARE_1: J1.4 ; port DIO_SPARE_1
DIO_SPARE_2: J1.6 ; port DIO_SPARE_2
DIO_SPARE_3: J1.8 ; port DIO_SPARE_3
DIO_SPARE_4: J1.10 ; port DIO_SPARE_4
DIO_SPARE_5: J1.12 ; port DIO_SPARE_5
DIO_SPARE_6: J1.14 ; port DIO_SPARE_6
DIO_SPARE_7: J1.16 ; port DIO_SPARE_7
FAULT_MUX_A: J2.58 ; port FAULT_MUX_A
FAULT_MUX_B: J2.60 ; port FAULT_MUX_B
FAULT_MUX_C: J2.62 ; port FAULT_MUX_C
FAULT_SENSE_HPB: J2.55 ; port FAULT_SENSE_HPB
FAULT_SENSE_IPB1: J2.51 ; port FAULT_SENSE_IPB1
FAULT_SENSE_IPB2: J2.53 ; port FAULT_SENSE_IPB2
GF_AMP_TEMP_F: J2.59 ; port GF_AMP_TEMP_F
GF_ANNODE_SEL_EN: J2.9 ; port GF_ANNODE_SEL_EN
GF_CHASSIS_SEL_EN: J2.11 ; port GF_CHASSIS_SEL_EN
GF_SIG: J2.47 ; port GF_SIG
GF_SOURCE_SEL_A: J2.1 ; port GF_SOURCE_SEL_A
GF_SOURCE_SEL_B: J2.3 ; port GF_SOURCE_SEL_B
GF_SOURCE_SEL_C: J2.5 ; port GF_SOURCE_SEL_C
GF_SOURCE_SEL_ENn: J2.7 ; port GF_SOURCE_SEL_ENn
HCB_MEDIA_EN: J1.30 ; port HCB_MEDIA_EN
HPB_5V_CURRENT: J2.34 ; port HPB_5V_CURRENT
HPB_5V_VOLTAGE: J2.30 ; port HPB_5V_VOLTAGE
HPB_24V_CURRENT: J2.26 ; port HPB_24V_CURRENT
HPB_24V_VOLTAGE: J2.22 ; port HPB_24V_VOLTAGE
HPB_CISCO1_CURRENT: J2.2 ; port HPB_CISCO1_CURRENT
HPB_CISCO1_EN: J1.49 ; port HPB_CISCO1_EN
HPB_CISCO2_CURRENT: J2.6 ; port HPB_CISCO2_CURRENT
HPB_CISCO2_EN: J1.51 ; port HPB_CISCO2_EN
HPB_ISO24V_CURRENT: J2.14 ; port HPB_ISO24V_CURRENT
HPB_MEDIA_CURRENT: J2.64 ; port HPB_MEDIA_CURRENT
HPB_SYNCBOX_CURRENT: J2.10 ; port HPB_SYNCBOX_CURRENT
HPB_SYNCBOX_EN: J1.53 ; port HPB_SYNCBOX_EN
HPB_TEMP0: J1.44 ; port HPB_TEMP0_F
HPB_TEMP1: J1.46 ; port HPB_TEMP1_F
HPB_TEMP2: J1.48 ; port HPB_TEMP2_F
HPB_TEMP3: J1.50 ; port HPB_TEMP3_F
HPB_TEMP4: J1.52 ; port HPB_TEMP4_F
HPB_VICOR1_TEMP: J1.38 ; port HPB_VICOR1_TEMP_F
HPB_VICOR2_TEMP: J1.40 ; port HPB_VICOR2_TEMP_F
HPB_VICOR3_TEMP: J1.42 ; port HPB_VICOR3_TEMP_F
I2C_SCL: J1.26 ; port I2C_SCL
I2C_SDA: J1.22 ; port I2C_SDA
IGB_TEMP_F: J2.57 ; port IGB_TEMP_F
INPUT_FET_LEFT_TEMP_F: J2.63 ; port INPUT_FET_LEFT_TEMP_F
INPUT_FET_RIGHT_TEMP_F: J2.61 ; port INPUT_FET_RIGHT_TEMP_F
IPB1_BOARD_TEMP: J1.34 ; port IPB1_BOARD_TEMP
IPB1_CHA_CURRENT_SET: J1.1 ; port IPB1_CHA_CURRENT_SET
IPB1_CHA_FET_EN: J1.21 ; port IPB1_CHA_FET_EN
IPB1_CHA_I: J2.15 ; port IPB1_CHA_I
IPB1_CHA_RLY_EN: J1.17 ; port IPB1_CHA_RLY_EN
IPB1_CHB_CURRENT_SET: J1.5 ; port IPB1_CHB_CURRENT_SET
IPB1_CHB_FET_EN: J1.29 ; port IPB1_CHB_FET_EN
IPB1_CHB_I: J2.23 ; port IPB1_CHB_I
IPB1_CHB_RLY_EN: J1.25 ; port IPB1_CHB_RLY_EN
IPB1_CHC_CURRENT_SET: J1.9 ; port IPB1_CHC_CURRENT_SET
IPB1_CHC_FET_EN: J1.37 ; port IPB1_CHC_FET_EN
IPB1_CHC_I: J2.31 ; port IPB1_CHC_I
IPB1_CHC_RLY_EN: J1.33 ; port IPB1_CHC_RLY_EN
IPB1_CHD_CURRENT_SET: J1.13 ; port IPB1_CHD_CURRENT_SET
IPB1_CHD_FET_EN: J1.45 ; port IPB1_CHD_FET_EN
IPB1_CHD_I: J2.39 ; port IPB1_CHD_I
IPB1_CHD_RLY_EN: J1.41 ; port IPB1_CHD_RLY_EN
IPB1_RESET: J2.36 ; port IPB1_RESET
IPB2_BOARD_TEMP: J1.36 ; port IPB2_BOARD_TEMP
IPB2_CHA_CURRENT_SET: J1.3 ; port IPB2_CHA_CURRENT_SET
IPB2_CHA_FET_EN: J1.23 ; port IPB2_CHA_FET_EN
IPB2_CHA_I: J2.19 ; port IPB2_CHA_I
IPB2_CHA_RLY_EN: J1.19 ; port IPB2_CHA_RLY_EN
IPB2_CHB_CURRENT_SET: J1.7 ; port IPB2_CHB_CURRENT_SET
IPB2_CHB_FET_EN: J1.31 ; port IPB2_CHB_FET_EN
IPB2_CHB_I: J2.27 ; port IPB2_CHB_I
IPB2_CHB_RLY_EN: J1.27 ; port IPB2_CHB_RLY_EN
IPB2_CHC_CURRENT_SET: J1.11 ; port IPB2_CHC_CURRENT_SET
IPB2_CHC_FET_EN: J1.39 ; port IPB2_CHC_FET_EN
IPB2_CHC_I: J2.35 ; port IPB2_CHC_I
IPB2_CHC_RLY_EN: J1.35 ; port IPB2_CHC_RLY_EN
IPB2_CHD_CURRENT_SET: J1.15 ; port IPB2_CHD_CURRENT_SET
IPB2_CHD_FET_EN: J1.47 ; port IPB2_CHD_FET_EN
IPB2_CHD_I: J2.43 ; port IPB2_CHD_I
IPB2_CHD_RLY_EN: J1.43 ; port IPB2_CHD_RLY_EN
IPB2_RESET: J2.38 ; port IPB2_RESET
MVC_L_CURRENT: J2.46 ; port MVC_L_CURRENT
MVC_L_VOLTAGE: J2.54 ; port MVC_L_VOLTAGE
MVC_R_CURRENT: J2.42 ; port MVC_R_CURRENT
MVC_R_VOLTAGE: J2.50 ; port MVC_R_VOLTAGE

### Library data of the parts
J1 J2 = CMP-002-00093-2: Conn Elevated Socket SKT 64 POS 2.54mm Solder ST Top Entry Thru-Hole Tube; Voltage Rating (AC): 550V; Current Rating: 6.9A; Number of Contacts: 64; Row Spacing: 0.1inch; Connector Type: Receptacle; Contact Resistance: 10mR

## Sheet CTI Breakout.SchDoc: MARS2 LVPS - BOB - CTI Breakout
size 431 x 279 mm; Organization: ORGANIZATION; Address1: APPLIED PHYSICS LAB; Address2: UNIVERSITY OF WASHINGTON; Address3: 1013 NE 40TH STREET; Address4: SEATTLE, WA 98105; DocumentNumber: 3; Revision: -; SheetNumber: 3; SheetTotal: 5; ENG_APP_DATE: --/--/--; DSN_APP_DATE: --/--/--; CHK_APP_DATE: --/--/--
Used 2 times, as channels CTI_1, CTI_2. Parts and nets are listed once, with the designators drawn on the sheet.
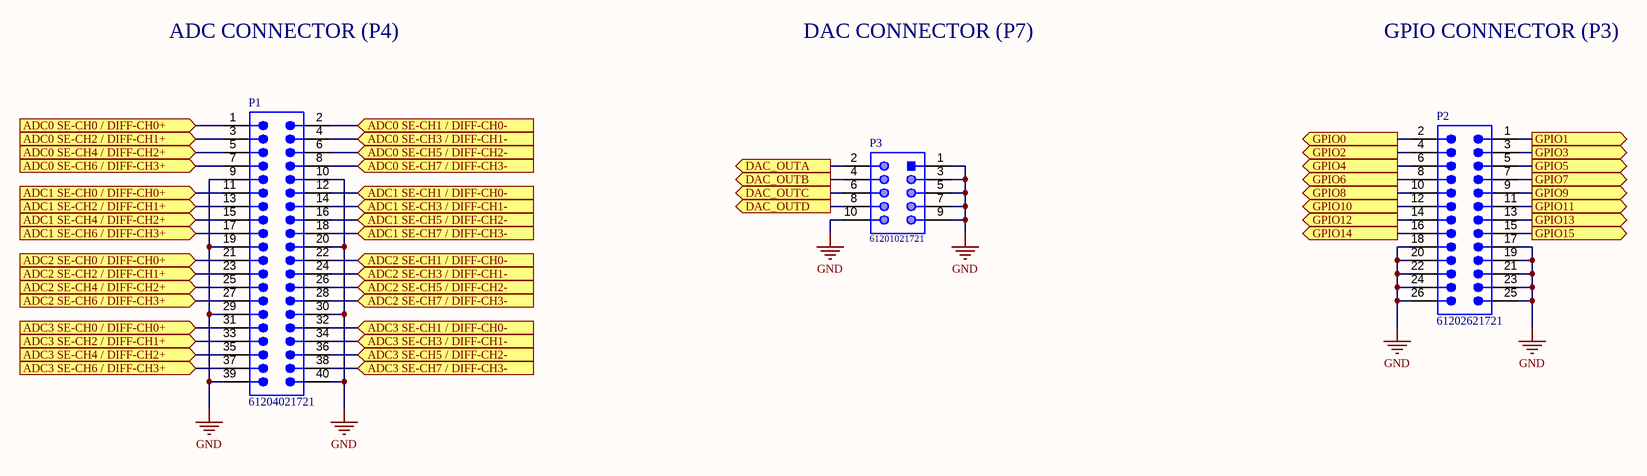
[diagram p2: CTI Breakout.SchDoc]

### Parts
P1  61204021721  [61204021721]
P2  61202621721  [61202621721]
P3  61201021721  [61201021721]

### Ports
ADC0 SE-CH0 / DIFF-CH0+ (in), ADC0 SE-CH1 / DIFF-CH0- (in), ADC0 SE-CH2 / DIFF-CH1+ (in), ADC0 SE-CH3 / DIFF-CH1- (in), ADC0 SE-CH4 / DIFF-CH2+ (in), ADC0 SE-CH5 / DIFF-CH2- (in), ADC0 SE-CH6 / DIFF-CH3+ (in), ADC0 SE-CH7 / DIFF-CH3- (in), ADC1 SE-CH0 / DIFF-CH0+ (in), ADC1 SE-CH1 / DIFF-CH0- (in), ADC1 SE-CH2 / DIFF-CH1+ (in), ADC1 SE-CH3 / DIFF-CH1- (in), ADC1 SE-CH4 / DIFF-CH2+ (in), ADC1 SE-CH5 / DIFF-CH2- (in), ADC1 SE-CH6 / DIFF-CH3+ (in), ADC1 SE-CH7 / DIFF-CH3- (in), ADC2 SE-CH0 / DIFF-CH0+ (in), ADC2 SE-CH1 / DIFF-CH0- (in), ADC2 SE-CH2 / DIFF-CH1+ (in), ADC2 SE-CH3 / DIFF-CH1- (in), ADC2 SE-CH4 / DIFF-CH2+ (in), ADC2 SE-CH5 / DIFF-CH2- (in), ADC2 SE-CH6 / DIFF-CH3+ (in), ADC2 SE-CH7 / DIFF-CH3- (in), ADC3 SE-CH0 / DIFF-CH0+ (in), ADC3 SE-CH1 / DIFF-CH0- (in), ADC3 SE-CH2 / DIFF-CH1+ (in), ADC3 SE-CH3 / DIFF-CH1- (in), ADC3 SE-CH4 / DIFF-CH2+ (in), ADC3 SE-CH5 / DIFF-CH2- (in), ADC3 SE-CH6 / DIFF-CH3+ (in), ADC3 SE-CH7 / DIFF-CH3- (in), DAC_OUTA (out), DAC_OUTB (out), DAC_OUTC (out), DAC_OUTD (out), GPIO0 (out), GPIO1 (out), GPIO2 (out), GPIO3 (out), GPIO4 (out), GPIO5 (out), GPIO6 (out), GPIO7 (out), GPIO8 (out), GPIO9 (out), GPIO10 (out), GPIO11 (out), GPIO12 (out), GPIO13 (out), GPIO14 (out), GPIO15 (out)

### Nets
GND: P1.9 P1.10 P1.19 P1.20 P1.29 P1.30 P1.39 P1.40 P2.17 P2.18 P2.19 P2.20 P2.21 P2.22 P2.23 P2.24 P2.25 P2.26 P3.1 P3.3 P3.5 P3.7 P3.9 P3.10
ADC0 SE-CH0 / DIFF-CH0+: P1.1 ; port ADC0 SE-CH0 / DIFF-CH0+
ADC0 SE-CH1 / DIFF-CH0-: P1.2 ; port ADC0 SE-CH1 / DIFF-CH0-
ADC0 SE-CH2 / DIFF-CH1+: P1.3 ; port ADC0 SE-CH2 / DIFF-CH1+
ADC0 SE-CH3 / DIFF-CH1-: P1.4 ; port ADC0 SE-CH3 / DIFF-CH1-
ADC0 SE-CH4 / DIFF-CH2+: P1.5 ; port ADC0 SE-CH4 / DIFF-CH2+
ADC0 SE-CH5 / DIFF-CH2-: P1.6 ; port ADC0 SE-CH5 / DIFF-CH2-
ADC0 SE-CH6 / DIFF-CH3+: P1.7 ; port ADC0 SE-CH6 / DIFF-CH3+
ADC0 SE-CH7 / DIFF-CH3-: P1.8 ; port ADC0 SE-CH7 / DIFF-CH3-
ADC1 SE-CH0 / DIFF-CH0+: P1.11 ; port ADC1 SE-CH0 / DIFF-CH0+
ADC1 SE-CH1 / DIFF-CH0-: P1.12 ; port ADC1 SE-CH1 / DIFF-CH0-
ADC1 SE-CH2 / DIFF-CH1+: P1.13 ; port ADC1 SE-CH2 / DIFF-CH1+
ADC1 SE-CH3 / DIFF-CH1-: P1.14 ; port ADC1 SE-CH3 / DIFF-CH1-
ADC1 SE-CH4 / DIFF-CH2+: P1.15 ; port ADC1 SE-CH4 / DIFF-CH2+
ADC1 SE-CH5 / DIFF-CH2-: P1.16 ; port ADC1 SE-CH5 / DIFF-CH2-
ADC1 SE-CH6 / DIFF-CH3+: P1.17 ; port ADC1 SE-CH6 / DIFF-CH3+
ADC1 SE-CH7 / DIFF-CH3-: P1.18 ; port ADC1 SE-CH7 / DIFF-CH3-
ADC2 SE-CH0 / DIFF-CH0+: P1.21 ; port ADC2 SE-CH0 / DIFF-CH0+
ADC2 SE-CH1 / DIFF-CH0-: P1.22 ; port ADC2 SE-CH1 / DIFF-CH0-
ADC2 SE-CH2 / DIFF-CH1+: P1.23 ; port ADC2 SE-CH2 / DIFF-CH1+
ADC2 SE-CH3 / DIFF-CH1-: P1.24 ; port ADC2 SE-CH3 / DIFF-CH1-
ADC2 SE-CH4 / DIFF-CH2+: P1.25 ; port ADC2 SE-CH4 / DIFF-CH2+
ADC2 SE-CH5 / DIFF-CH2-: P1.26 ; port ADC2 SE-CH5 / DIFF-CH2-
ADC2 SE-CH6 / DIFF-CH3+: P1.27 ; port ADC2 SE-CH6 / DIFF-CH3+
ADC2 SE-CH7 / DIFF-CH3-: P1.28 ; port ADC2 SE-CH7 / DIFF-CH3-
ADC3 SE-CH0 / DIFF-CH0+: P1.31 ; port ADC3 SE-CH0 / DIFF-CH0+
ADC3 SE-CH1 / DIFF-CH0-: P1.32 ; port ADC3 SE-CH1 / DIFF-CH0-
ADC3 SE-CH2 / DIFF-CH1+: P1.33 ; port ADC3 SE-CH2 / DIFF-CH1+
ADC3 SE-CH3 / DIFF-CH1-: P1.34 ; port ADC3 SE-CH3 / DIFF-CH1-
ADC3 SE-CH4 / DIFF-CH2+: P1.35 ; port ADC3 SE-CH4 / DIFF-CH2+
ADC3 SE-CH5 / DIFF-CH2-: P1.36 ; port ADC3 SE-CH5 / DIFF-CH2-
ADC3 SE-CH6 / DIFF-CH3+: P1.37 ; port ADC3 SE-CH6 / DIFF-CH3+
ADC3 SE-CH7 / DIFF-CH3-: P1.38 ; port ADC3 SE-CH7 / DIFF-CH3-
DAC_OUTA: P3.2 ; port DAC_OUTA
DAC_OUTB: P3.4 ; port DAC_OUTB
DAC_OUTC: P3.6 ; port DAC_OUTC
DAC_OUTD: P3.8 ; port DAC_OUTD
GPIO0: P2.2 ; port GPIO0
GPIO1: P2.1 ; port GPIO1
GPIO2: P2.4 ; port GPIO2
GPIO3: P2.3 ; port GPIO3
GPIO4: P2.6 ; port GPIO4
GPIO5: P2.5 ; port GPIO5
GPIO6: P2.8 ; port GPIO6
GPIO7: P2.7 ; port GPIO7
GPIO8: P2.10 ; port GPIO8
GPIO9: P2.9 ; port GPIO9
GPIO10: P2.12 ; port GPIO10
GPIO11: P2.11 ; port GPIO11
GPIO12: P2.14 ; port GPIO12
GPIO13: P2.13 ; port GPIO13
GPIO14: P2.16 ; port GPIO14
GPIO15: P2.15 ; port GPIO15

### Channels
CTI_1: designators end in A; ports ADC0 SE-CH0 / DIFF-CH0+=IPB1_CHA_I ADC0 SE-CH1 / DIFF-CH0-=IPB1_CHB_I ADC0 SE-CH2 / DIFF-CH1+=IPB1_CHC_I ADC0 SE-CH3 / DIFF-CH1-=IPB1_CHD_I ADC0 SE-CH4 / DIFF-CH2+=HPB_MEDIA_CURRENT_BUF ADC0 SE-CH5 / DIFF-CH2-=NetP1A_6 ADC0 SE-CH6 / DIFF-CH3+=NetP1A_7 ADC0 SE-CH7 / DIFF-CH3-=NetP1A_8 ADC1 SE-CH0 / DIFF-CH0+=GF_SIG ADC1 SE-CH1 / DIFF-CH0-=NetP1A_12 ADC1 SE-CH2 / DIFF-CH1+=NetP1A_13 ADC1 SE-CH3 / DIFF-CH1-=NetP1A_14 ADC1 SE-CH4 / DIFF-CH2+=NetP1A_15 ADC1 SE-CH5 / DIFF-CH2-=NetP1A_16 ADC1 SE-CH6 / DIFF-CH3+=NetP1A_17 ADC1 SE-CH7 / DIFF-CH3-=NetP1A_18 ADC2 SE-CH0 / DIFF-CH0+=NetP1A_21 ADC2 SE-CH1 / DIFF-CH0-=GF_AMP_TEMP_F_BUF ADC2 SE-CH2 / DIFF-CH1+=IGB_TEMP_F_BUF ADC2 SE-CH3 / DIFF-CH1-=HPB_VICOR1_TEMP_F_BUF ADC2 SE-CH4 / DIFF-CH2+=HPB_VICOR2_TEMP_F_BUF ADC2 SE-CH5 / DIFF-CH2-=HPB_VICOR3_TEMP_F_BUF ADC2 SE-CH6 / DIFF-CH3+=HPB_TEMP0_F_BUF ADC2 SE-CH7 / DIFF-CH3-=HPB_TEMP1_F_BUF ADC3 SE-CH0 / DIFF-CH0+=HPB_TEMP2_F_BUF ADC3 SE-CH1 / DIFF-CH0-=HPB_TEMP3_F_BUF ADC3 SE-CH2 / DIFF-CH1+=HPB_TEMP4_F_BUF ADC3 SE-CH3 / DIFF-CH1-=INPUT_FET_LEFT_TEMP_F_BUF ADC3 SE-CH4 / DIFF-CH2+=INPUT_FET_RIGHT_TEMP_F_BUF ADC3 SE-CH5 / DIFF-CH2-=IPB1_BOARD_TEMP_BUF ADC3 SE-CH6 / DIFF-CH3+=IPB2_BOARD_TEMP_BUF ADC3 SE-CH7 / DIFF-CH3-=NetP1A_38 DAC_OUTA=IPB1_CHA_CURRENT_SET DAC_OUTB=IPB1_CHB_CURRENT_SET DAC_OUTC=IPB1_CHC_CURRENT_SET DAC_OUTD=IPB1_CHD_CURRENT_SET GPIO0=GF_SOURCE_SEL_A GPIO1=GF_SOURCE_SEL_B GPIO2=GF_SOURCE_SEL_C GPIO3=GF_SOURCE_SEL_ENn GPIO4=GF_ANNODE_SEL_EN GPIO5=GF_CHASSIS_SEL_EN GPIO6=IPB1_CHA_RLY_EN GPIO7=IPB1_CHA_FET_EN GPIO8=IPB1_CHB_RLY_EN GPIO9=IPB1_CHB_FET_EN GPIO10=IPB1_CHC_RLY_EN GPIO11=IPB1_CHC_FET_EN GPIO12=IPB1_CHD_RLY_EN GPIO13=IPB1_CHD_FET_EN GPIO14=IPB1_RESET GPIO15=NetJ19_1
CTI_2: designators end in B; ports ADC0 SE-CH0 / DIFF-CH0+=IPB2_CHA_I ADC0 SE-CH1 / DIFF-CH0-=IPB2_CHB_I ADC0 SE-CH2 / DIFF-CH1+=IPB2_CHC_I ADC0 SE-CH3 / DIFF-CH1-=IPB2_CHD_I ADC0 SE-CH4 / DIFF-CH2+=HPB_CISCO1_CURRENT_BUF ADC0 SE-CH5 / DIFF-CH2-=HPB_CISCO2_CURRENT_BUF ADC0 SE-CH6 / DIFF-CH3+=HPB_SYNCBOX_CURRENT_BUF ADC0 SE-CH7 / DIFF-CH3-=HPB_ISO24V_CURRENT_BUF ADC1 SE-CH0 / DIFF-CH0+=HPB_24V_CURRENT_BUF ADC1 SE-CH1 / DIFF-CH0-=HPB_5V_CURRENT_BUF ADC1 SE-CH2 / DIFF-CH1+=HPB_24V_VOLTAGE_BUF ADC1 SE-CH3 / DIFF-CH1-=HPB_5V_VOLTAGE_BUF ADC1 SE-CH4 / DIFF-CH2+=24V_UNSWCH_BUS_CURRENT_BUF ADC1 SE-CH5 / DIFF-CH2-=MVC_L_CURRENT ADC1 SE-CH6 / DIFF-CH3+=MVC_R_CURRENT ADC1 SE-CH7 / DIFF-CH3-=MVC_L_VOLTAGE_BUF ADC2 SE-CH0 / DIFF-CH0+=MVC_R_VOLTAGE_BUF ADC2 SE-CH1 / DIFF-CH0-=NetP1B_22 ADC2 SE-CH2 / DIFF-CH1+=NetP1B_23 ADC2 SE-CH3 / DIFF-CH1-=NetP1B_24 ADC2 SE-CH4 / DIFF-CH2+=NetP1B_25 ADC2 SE-CH5 / DIFF-CH2-=NetP1B_26 ADC2 SE-CH6 / DIFF-CH3+=NetP1B_27 ADC2 SE-CH7 / DIFF-CH3-=NetP1B_28 ADC3 SE-CH0 / DIFF-CH0+=FAULT_SENSE_HPB ADC3 SE-CH1 / DIFF-CH0-=FAULT_SENSE_IPB1 ADC3 SE-CH2 / DIFF-CH1+=FAULT_SENSE_IPB2 ADC3 SE-CH3 / DIFF-CH1-=NetP1B_34 ADC3 SE-CH4 / DIFF-CH2+=NetP1B_35 ADC3 SE-CH5 / DIFF-CH2-=NetP1B_36 ADC3 SE-CH6 / DIFF-CH3+=NetP1B_37 ADC3 SE-CH7 / DIFF-CH3-=NetP1B_38 DAC_OUTA=IPB2_CHA_CURRENT_SET DAC_OUTB=IPB2_CHB_CURRENT_SET DAC_OUTC=IPB2_CHC_CURRENT_SET DAC_OUTD=IPB2_CHD_CURRENT_SET GPIO0=IPB2_CHA_RLY_EN GPIO1=IPB2_CHA_FET_EN GPIO2=IPB2_CHB_RLY_EN GPIO3=IPB2_CHB_FET_EN GPIO4=IPB2_CHC_RLY_EN GPIO5=IPB2_CHC_FET_EN GPIO6=IPB2_CHD_RLY_EN GPIO7=IPB2_CHD_FET_EN GPIO8=HPB_CISCO1_EN GPIO9=HPB_CISCO2_EN GPIO10=HPB_SYNCBOX_EN GPIO11=HCB_MEDIA_EN GPIO12=FAULT_MUX_A GPIO13=FAULT_MUX_B GPIO14=FAULT_MUX_C GPIO15=IPB2_RESET

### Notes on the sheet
- ADC CONNECTOR (P4)
- DAC CONNECTOR (P7)
- GPIO CONNECTOR (P3)

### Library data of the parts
P1 = CMP-002-00158-1: WR-BHD Angled Male, Box Header, Through Hole, 2 Rows, 40 Contacts, 2.54mm Pitch; Number of Contacts: 40; Current Rating: 3A; Voltage Rating: 250V
P2 = CMP-002-00157-1: WR-BHD Angled Male, Box Header, Through Hole, 2 Rows, 26 Contacts, 2.54mm Pitch; Number of Contacts: 26; Current Rating: 3A; Voltage Rating: 250V; Row Spacing: 0.1inch
P3 = CMP-002-00155-1: WR-BHD Angled Male, Box Header, Through Hole, 2 Rows, 10 Contacts, 2.54mm Pitch; Voltage Rating: 250V; Current Rating: 3A; Number of Contacts: 10

## Sheet Baycat Breakout.SchDoc: MARS2 LVPS - BOB - Baycat Breakout
size 431 x 279 mm; Organization: ORGANIZATION; Address1: APPLIED PHYSICS LAB; Address2: UNIVERSITY OF WASHINGTON; Address3: 1013 NE 40TH STREET; Address4: SEATTLE, WA 98105; DocumentNumber: 4; Revision: -; SheetNumber: 4; SheetTotal: 5; ENG_APP_DATE: --/--/--; DSN_APP_DATE: --/--/--; CHK_APP_DATE: --/--/--
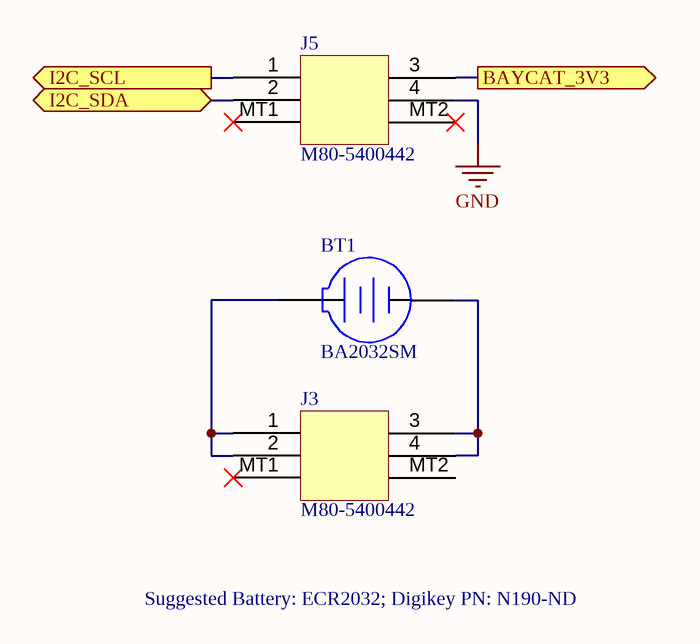
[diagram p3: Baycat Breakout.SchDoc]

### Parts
BT1  BA2032SM  [MPD-BA2032SM_V]
J3  M80-5400442  [M80-5400442-Footprint-1]
J5  M80-5400442  [M80-5400442-Footprint-1]

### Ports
BAYCAT_3V3 (out), I2C_SCL (out), I2C_SDA (bidir)

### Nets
GND: J5.4
BAYCAT_3V3: J5.3 ; port BAYCAT_3V3
I2C_SCL: J5.1 ; port I2C_SCL
I2C_SDA: J5.2 ; port I2C_SDA
NetBT1_1: BT1.1(+) J3.1 J3.2
NetBT1_2: BT1.2(-) J3.3 J3.4

Not connected (* = marked no-connect by the designer): J3 MT1* MT2; J5 MT1* MT2*

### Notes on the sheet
- Suggested Battery: ECR2032; Digikey PN: N190-ND

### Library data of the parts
BT1 = CMP-002-00003-2: Coin Cell Holder, 1 Cell, -40 to 225 degC, 2-Pin SMD, RoHS, Tray; Manufacturer: Memory Protection Devices; Connector Type: BatteryHolder
J3 J5 = CMP-002-00095-3: HARWIN - M80-5400442 - Wire-To-Board Connector, 2 mm, 4 Contacts, Header, Datamate J-Tek M80 Series, Through Hole, 2 Rows; Maximum Voltage: 800V; Gender: Male; Number of Contacts: 4; Pitch: 2mm; Current Rating: 2.2A; Contact Resistance: 25mR; Insulation Resistance: 100MR

## Sheet Test Points.SchDoc: MARS2 LVPS - BOB - Test Points
size 431 x 279 mm; Organization: ORGANIZATION; Address1: APPLIED PHYSICS LAB; Address2: UNIVERSITY OF WASHINGTON; Address3: 1013 NE 40TH STREET; Address4: SEATTLE, WA 98105; DocumentNumber: 5; Revision: -; SheetNumber: 5; SheetTotal: 5; ENG_APP_DATE: --/--/--; DSN_APP_DATE: --/--/--; CHK_APP_DATE: --/--/--
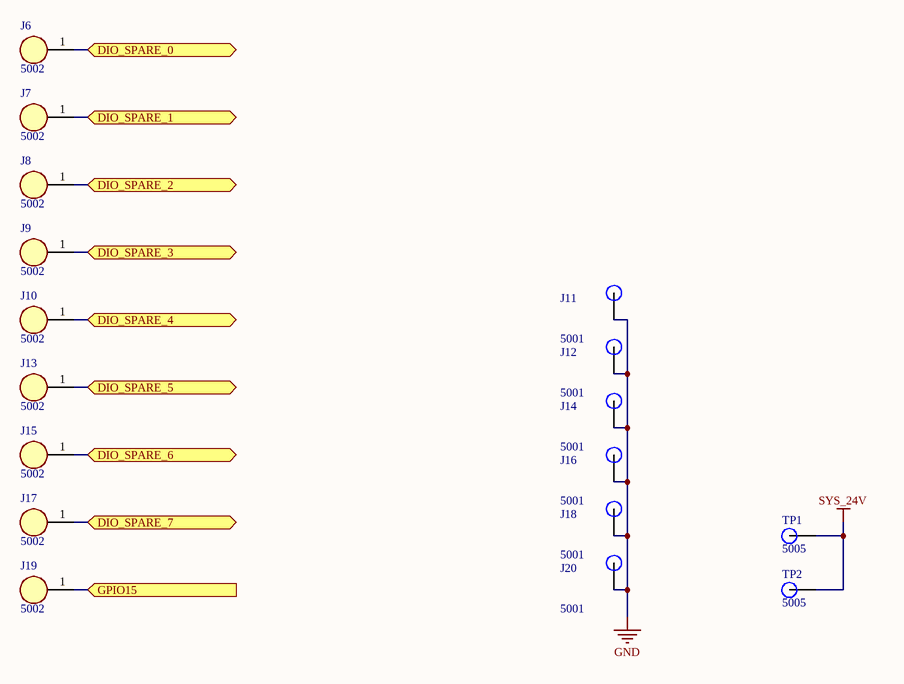
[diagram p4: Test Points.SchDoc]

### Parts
J6  5002  [FP-5002-MFG]
J7  5002  [FP-5002-MFG]
J8  5002  [FP-5002-MFG]
J9  5002  [FP-5002-MFG]
J10  5002  [FP-5002-MFG]
J11  5001  [FP-5001-MFG]
J12  5001  [FP-5001-MFG]
J13  5002  [FP-5002-MFG]
J14  5001  [FP-5001-MFG]
J15  5002  [FP-5002-MFG]
J16  5001  [FP-5001-MFG]
J17  5002  [FP-5002-MFG]
J18  5001  [FP-5001-MFG]
J19  5002  [FP-5002-MFG]
J20  5001  [FP-5001-MFG]
TP1  5005  [TestPoint-5005-Footprint-1]
TP2  5005  [TestPoint-5005-Footprint-1]

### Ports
DIO_SPARE_0 (bidir), DIO_SPARE_1 (bidir), DIO_SPARE_2 (bidir), DIO_SPARE_3 (bidir), DIO_SPARE_4 (bidir), DIO_SPARE_5 (bidir), DIO_SPARE_6 (bidir), DIO_SPARE_7 (bidir), GPIO15 (in)

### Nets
GND: J11.1 J12.1 J14.1 J16.1 J18.1 J20.1
SYS_24V: TP1.1 TP2.1
DIO_SPARE_0: J6.1 ; port DIO_SPARE_0
DIO_SPARE_1: J7.1 ; port DIO_SPARE_1
DIO_SPARE_2: J8.1 ; port DIO_SPARE_2
DIO_SPARE_3: J9.1 ; port DIO_SPARE_3
DIO_SPARE_4: J10.1 ; port DIO_SPARE_4
DIO_SPARE_5: J13.1 ; port DIO_SPARE_5
DIO_SPARE_6: J15.1 ; port DIO_SPARE_6
DIO_SPARE_7: J17.1 ; port DIO_SPARE_7
NetJ19_1: J19.1 ; port GPIO15

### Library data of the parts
J6-J10 J13 J15 J17 J19 = CMP-002-00083-3: TEST POINT PC MINI .040D WHITE; Body Material: Bronze
J11 J12 J14 J16 J18 J20 = CMP-001-0002-3: TEST POINT PC MINI .040D BLACK
TP1 TP2 = CMP-001-0000-5: PC TEST POINT COMPACT RED; Inside Diameter: 1.78mm; Hole Diameter: 1.6mm

## Sheet 8CH-Voltage-Buffer.SchDoc: Voltage Buffers (8CH)
size 431 x 279 mm; Organization: ORGANIZATION; Address1: APPLIED PHYSICS LAB; Address2: UNIVERSITY OF WASHINGTON; Address3: 1013 NE 40TH STREET; Address4: SEATTLE, WA 98105; Revision: -; ENG_APP_DATE: --/--/--; DSN_APP_DATE: --/--/--; CHK_APP_DATE: --/--/--
Used 4 times, as channels Voltage Buffer - 4CH Bank 1, Voltage Buffer - 4CH Bank 2, Voltage Buffer - 4CH Bank 3, Voltage Buffer - 4CH Bank 4. Parts and nets are listed once, with the designators drawn on the sheet.
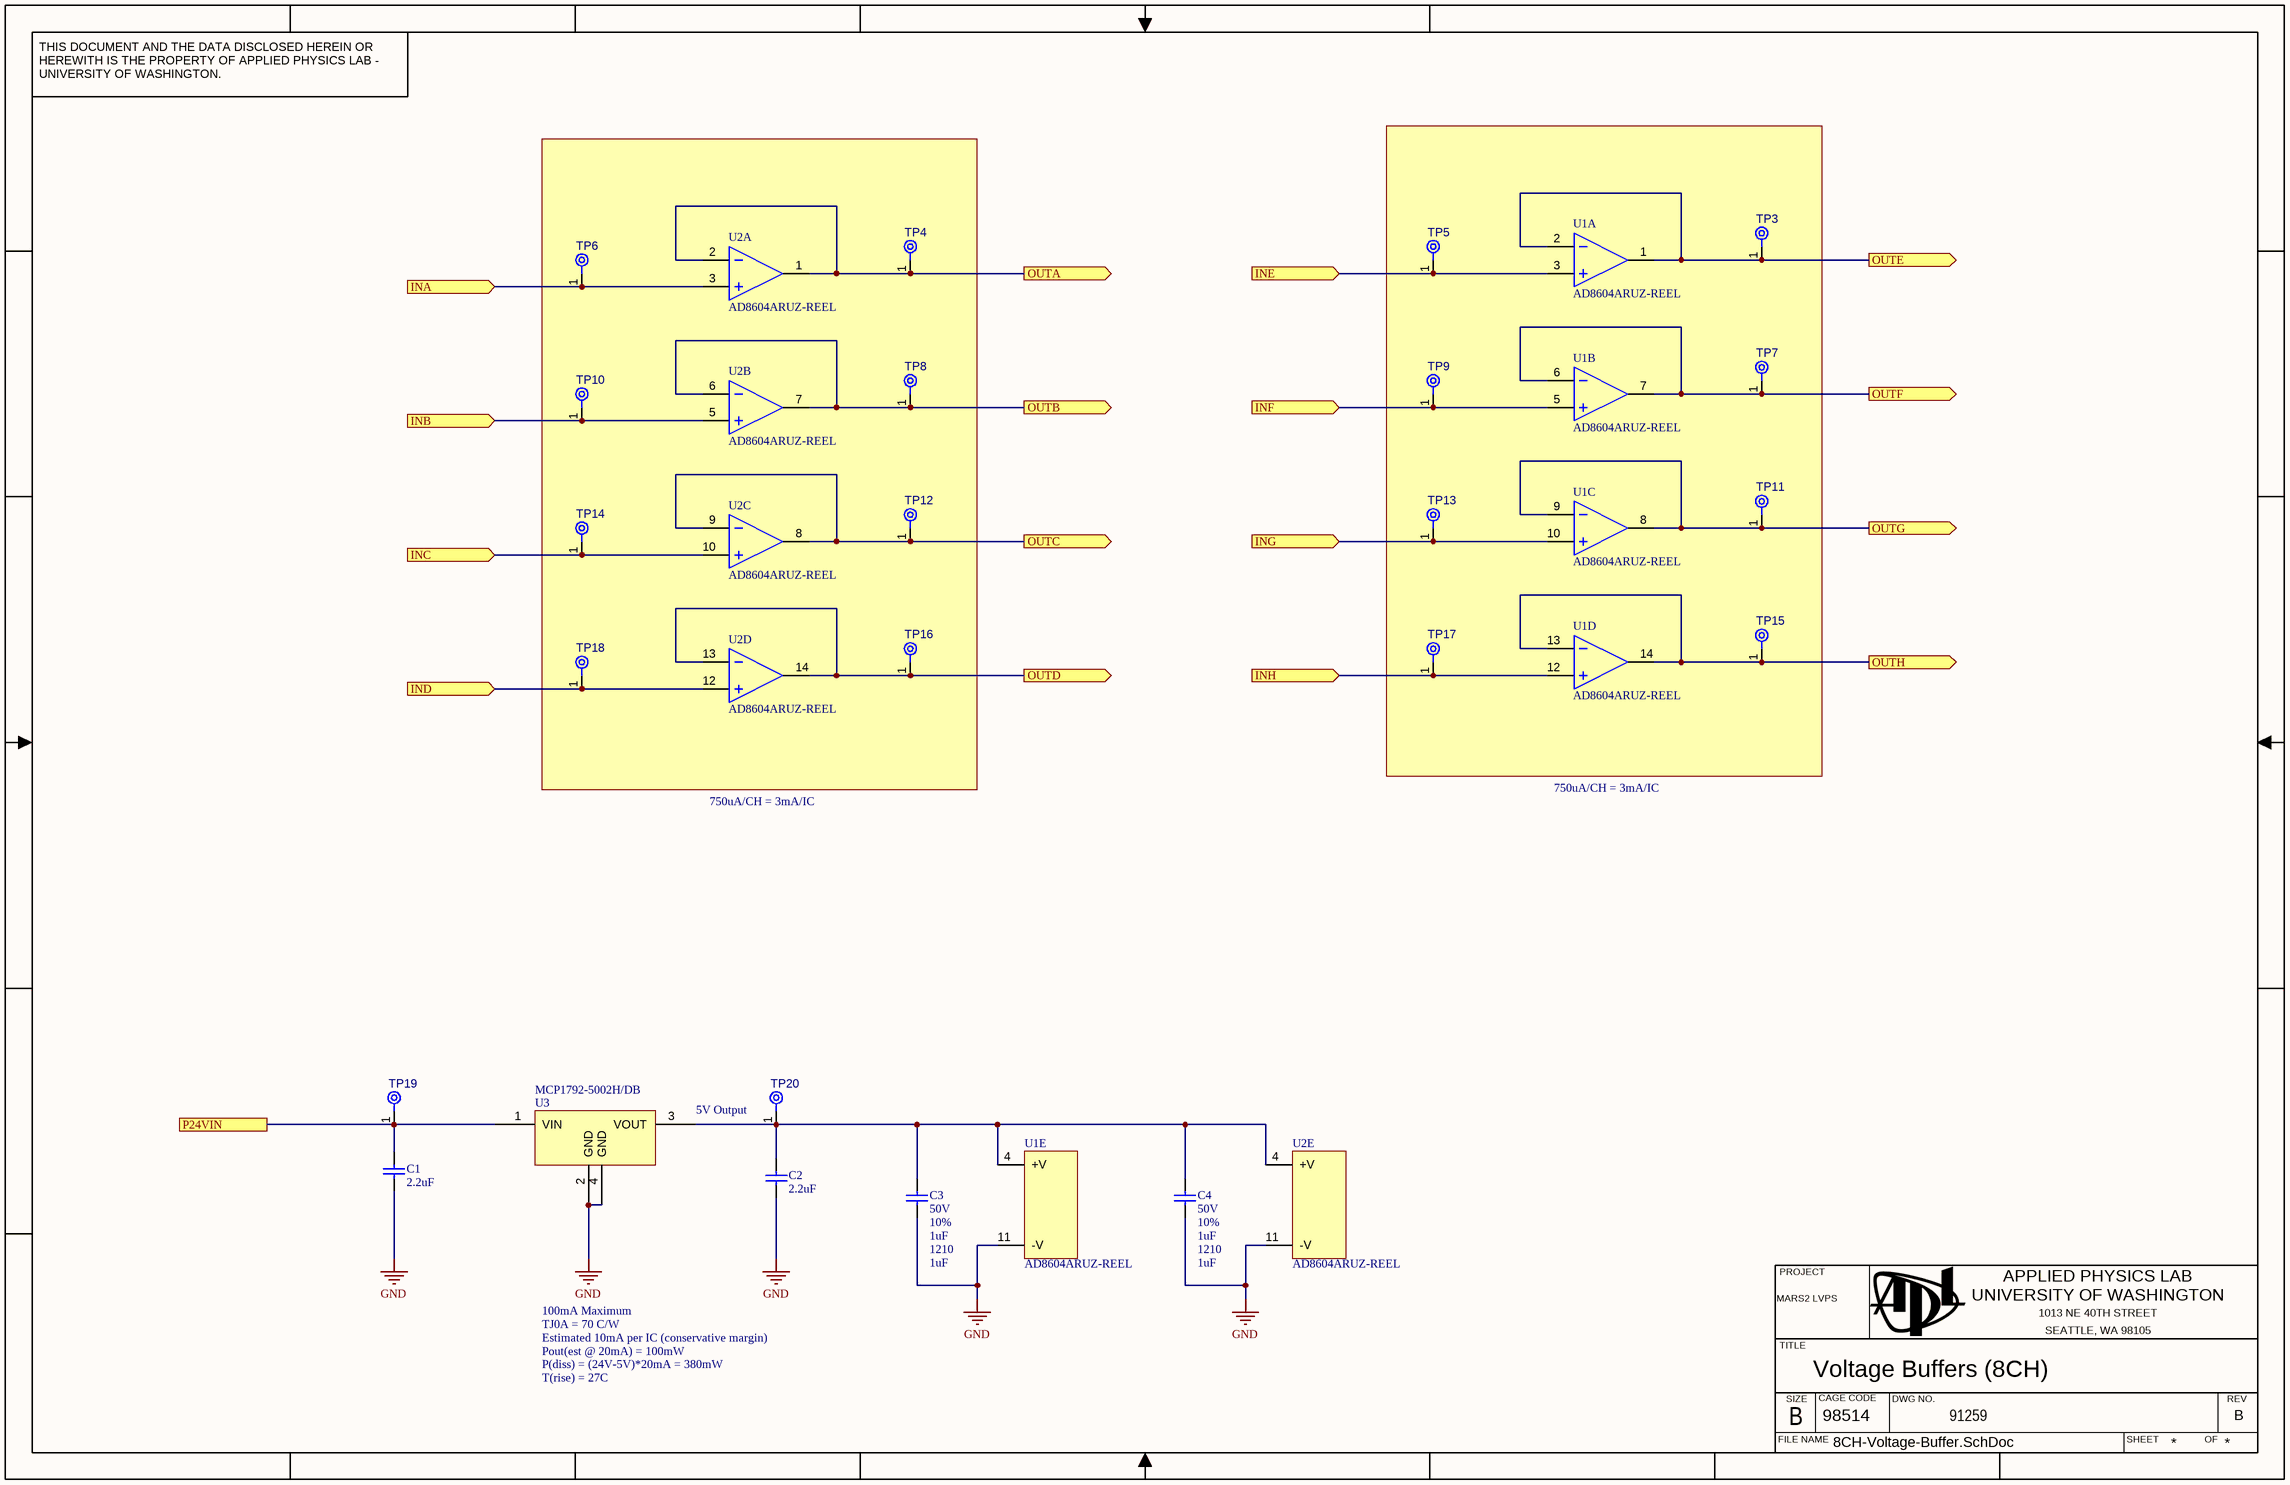
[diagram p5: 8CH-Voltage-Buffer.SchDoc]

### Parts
C1  value 2.2uF  [CAPC2013X95X50ML10T25]  (hidden comment: Capacitor 2.2uF 10%, 50V, X7R, 0805)
C2  value 2.2uF  [CAPC2013X95X50ML10T25]  (hidden comment: Capacitor 2.2uF 10%, 50V, X7R, 0805)
C3  value 1uF  Voltage Rating: 50V  Tolerance: 10%  Capacitance: 1uF  Case/Package: 1210  [CAPC3225X270X30ML30]  (hidden comment: Capacitor 1uF 10%, 50V, X7R, 1210)
C4  value 1uF  Voltage Rating: 50V  Tolerance: 10%  Capacitance: 1uF  Case/Package: 1210  [CAPC3225X270X30ML30]  (hidden comment: Capacitor 1uF 10%, 50V, X7R, 1210)
TP3  TPAD6R-CIRCLED  [TP06R - Circled]  (value not drawn)  (no BOM)
TP4  TPAD6R-CIRCLED  [TP06R - Circled]  (value not drawn)  (no BOM)
TP5  TPAD6R-CIRCLED  [TP06R - Circled]  (value not drawn)  (no BOM)
TP6  TPAD6R-CIRCLED  [TP06R - Circled]  (value not drawn)  (no BOM)
TP7  TPAD6R-CIRCLED  [TP06R - Circled]  (value not drawn)  (no BOM)
TP8  TPAD6R-CIRCLED  [TP06R - Circled]  (value not drawn)  (no BOM)
TP9  TPAD6R-CIRCLED  [TP06R - Circled]  (value not drawn)  (no BOM)
TP10  TPAD6R-CIRCLED  [TP06R - Circled]  (value not drawn)  (no BOM)
TP11  TPAD6R-CIRCLED  [TP06R - Circled]  (value not drawn)  (no BOM)
TP12  TPAD6R-CIRCLED  [TP06R - Circled]  (value not drawn)  (no BOM)
TP13  TPAD6R-CIRCLED  [TP06R - Circled]  (value not drawn)  (no BOM)
TP14  TPAD6R-CIRCLED  [TP06R - Circled]  (value not drawn)  (no BOM)
TP15  TPAD6R-CIRCLED  [TP06R - Circled]  (value not drawn)  (no BOM)
TP16  TPAD6R-CIRCLED  [TP06R - Circled]  (value not drawn)  (no BOM)
TP17  TPAD6R-CIRCLED  [TP06R - Circled]  (value not drawn)  (no BOM)
TP18  TPAD6R-CIRCLED  [TP06R - Circled]  (value not drawn)  (no BOM)
TP19  TPAD6R-CIRCLED  [TP06R - Circled]  (value not drawn)  (no BOM)
TP20  TPAD6R-CIRCLED  [TP06R - Circled]  (value not drawn)  (no BOM)
U1  AD8604ARUZ-REEL  [ADI-RU-14_M]  (parts A,B,C,D,E of 5)
U2  AD8604ARUZ-REEL  [ADI-RU-14_M]  (parts A,B,C,D,E of 5)
U3  MCP1792-5002H/DB  [SOT230P700X180-4M]

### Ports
INA (in), INB (in), INC (in), IND (in), INE (in), INF (in), ING (in), INH (in), OUTA (out), OUTB (out), OUTC (out), OUTD (out), OUTE (out), OUTF (out), OUTG (out), OUTH (out), P24VIN

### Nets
GND: C1.1 C2.1 C3.2 C4.2 U1.11(-V) U2.11(-V) U3.2(GND) U3.4(GND)
INA: TP6.1(TP) U2.3(+IN_A) ; port INA
INB: TP10.1(TP) U2.5(+IN_B) ; port INB
INC: TP14.1(TP) U2.10(+IN_C) ; port INC
IND: TP18.1(TP) U2.12(+IN_D) ; port IND
INE: TP5.1(TP) U1.3(+IN_A) ; port INE
INF: TP9.1(TP) U1.5(+IN_B) ; port INF
ING: TP13.1(TP) U1.10(+IN_C) ; port ING
INH: TP17.1(TP) U1.12(+IN_D) ; port INH
OUTA: TP4.1(TP) U2.1(OUT_A) U2.2(-IN_A) ; port OUTA
OUTB: TP8.1(TP) U2.6(-IN_B) U2.7(OUT_B) ; port OUTB
OUTC: TP12.1(TP) U2.8(OUT_C) U2.9(-IN_C) ; port OUTC
OUTD: TP16.1(TP) U2.13(-IN_D) U2.14(OUT_D) ; port OUTD
OUTE: TP3.1(TP) U1.1(OUT_A) U1.2(-IN_A) ; port OUTE
OUTF: TP7.1(TP) U1.6(-IN_B) U1.7(OUT_B) ; port OUTF
OUTG: TP11.1(TP) U1.8(OUT_C) U1.9(-IN_C) ; port OUTG
OUTH: TP15.1(TP) U1.13(-IN_D) U1.14(OUT_D) ; port OUTH
P24VIN: C1.2 TP19.1(TP) U3.1(VIN) ; port P24VIN
NetC2_2: C2.2 C3.1 C4.1 TP20.1(TP) U1.4(+V) U2.4(+V) U3.3(VOUT)

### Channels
Voltage Buffer - 4CH Bank 1: designators end in A; ports INA=HPB_CISCO1_CURRENT INB=HPB_CISCO2_CURRENT INC=HPB_SYNCBOX_CURRENT IND=HPB_ISO24V_CURRENT INE=HPB_24V_CURRENT INF=HPB_5V_CURRENT ING=HPB_24V_VOLTAGE INH=HPB_5V_VOLTAGE OUTA=HPB_CISCO1_CURRENT_BUF OUTB=HPB_CISCO2_CURRENT_BUF OUTC=HPB_SYNCBOX_CURRENT_BUF OUTD=HPB_ISO24V_CURRENT_BUF OUTE=HPB_24V_CURRENT_BUF OUTF=HPB_5V_CURRENT_BUF OUTG=HPB_24V_VOLTAGE_BUF OUTH=HPB_5V_VOLTAGE_BUF P24VIN=NetC1A_2
Voltage Buffer - 4CH Bank 2: designators end in B; ports INA=HPB_TEMP2 INB=HPB_TEMP3 INC=HPB_TEMP4 IND=INPUT_FET_LEFT_TEMP_F INE=INPUT_FET_RIGHT_TEMP_F INF=IPB1_BOARD_TEMP ING=IPB2_BOARD_TEMP INH=NetTP17B_1 OUTA=HPB_TEMP2_F_BUF OUTB=HPB_TEMP3_F_BUF OUTC=HPB_TEMP4_F_BUF OUTD=INPUT_FET_LEFT_TEMP_F_BUF OUTE=INPUT_FET_RIGHT_TEMP_F_BUF OUTF=IPB1_BOARD_TEMP_BUF OUTG=IPB2_BOARD_TEMP_BUF OUTH=NetTP15B_1 P24VIN=NetC1B_2
Voltage Buffer - 4CH Bank 3: designators end in C; ports INA=HPB_MEDIA_CURRENT INB=GF_AMP_TEMP_F INC=IGB_TEMP_F IND=HPB_VICOR1_TEMP INE=HPB_VICOR2_TEMP INF=HPB_VICOR3_TEMP ING=HPB_TEMP0 INH=HPB_TEMP1 OUTA=HPB_MEDIA_CURRENT_BUF OUTB=GF_AMP_TEMP_F_BUF OUTC=IGB_TEMP_F_BUF OUTD=HPB_VICOR1_TEMP_F_BUF OUTE=HPB_VICOR2_TEMP_F_BUF OUTF=HPB_VICOR3_TEMP_F_BUF OUTG=HPB_TEMP0_F_BUF OUTH=HPB_TEMP1_F_BUF P24VIN=NetC1C_2
Voltage Buffer - 4CH Bank 4: designators end in D; ports INA=24V_UNSWCH_BUS_CURRENT INB=MVC_L_VOLTAGE INC=MVC_R_VOLTAGE IND=NetR29_2 INE=NetR28_2 INF=NetR27_2 ING=NetR26_2 INH=NetR1_2 OUTA=24V_UNSWCH_BUS_CURRENT_BUF OUTB=MVC_L_VOLTAGE_BUF OUTC=MVC_R_VOLTAGE_BUF OUTD=NetTP16D_1 OUTE=NetTP3D_1 OUTF=NetTP7D_1 OUTG=NetTP11D_1 OUTH=NetTP15D_1 P24VIN=NetC1D_2

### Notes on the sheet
- 750uA/CH = 3mA/IC
- 5V Output
- Estimated 10mA per IC (conservative margin)
- 100mA Maximum
- TJ0A = 70 C/W
- Pout(est @ 20mA) = 100mW
- P(diss) = (24V-5V)*20mA = 380mW
- T(rise) = 27C

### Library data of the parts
C1 C2 = CMP-001-00167-10: Chip Capacitor, 2.2uF, 10%, 50 V, X7R 0805 (2012 Metric); Capacitor Type: Ceramic; Decade: 1uF
C3 C4 = CMP-001-00181-9: Chip Capacitor, 1uF, 10%, 50 V, X7R 1210 (3225 Metric); Capacitor Type: Ceramic
TP3-TP20 = CMP-00028-00014-1: 0.6mm round with a silkscreen circle.
U1 U2 = CMP-014-00034-2: IC OPAMP GP 8.4MHZ RRO 14TSSOP; Common Mode Rejection Ratio: 74dB; Input Bias Current: 0.2pA; Quiescent Current: 1.2mA; Input Offset Voltage (Vos): 600uV; Min Supply Voltage: 2.7V; Operating Supply Current: 4.8mA; Voltage Gain: 98.06dB; Input Voltage Noise Density: 33nV/sqrt Hz; Number of Channels: 4; Slew Rate: 6V/µs; Power Supply Rejection Ratio (PSRR): 75dB; Max Supply Voltage: 5.5V; Output Current per Channel: 50mA
U3 = CMP-019-00076-2: High input voltage regulator 5.0 V 3Ld SOT-223 3 SOT-223 TUBE RoHS Compliant: Yes; Min Input Voltage: 6.2V; Max Input Voltage: 55V; Max Ouput Current: 100mA; Dropout Voltage: 1.2V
